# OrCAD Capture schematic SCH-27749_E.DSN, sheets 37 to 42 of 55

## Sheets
37 T4240 SerDes 1 & 2: size C
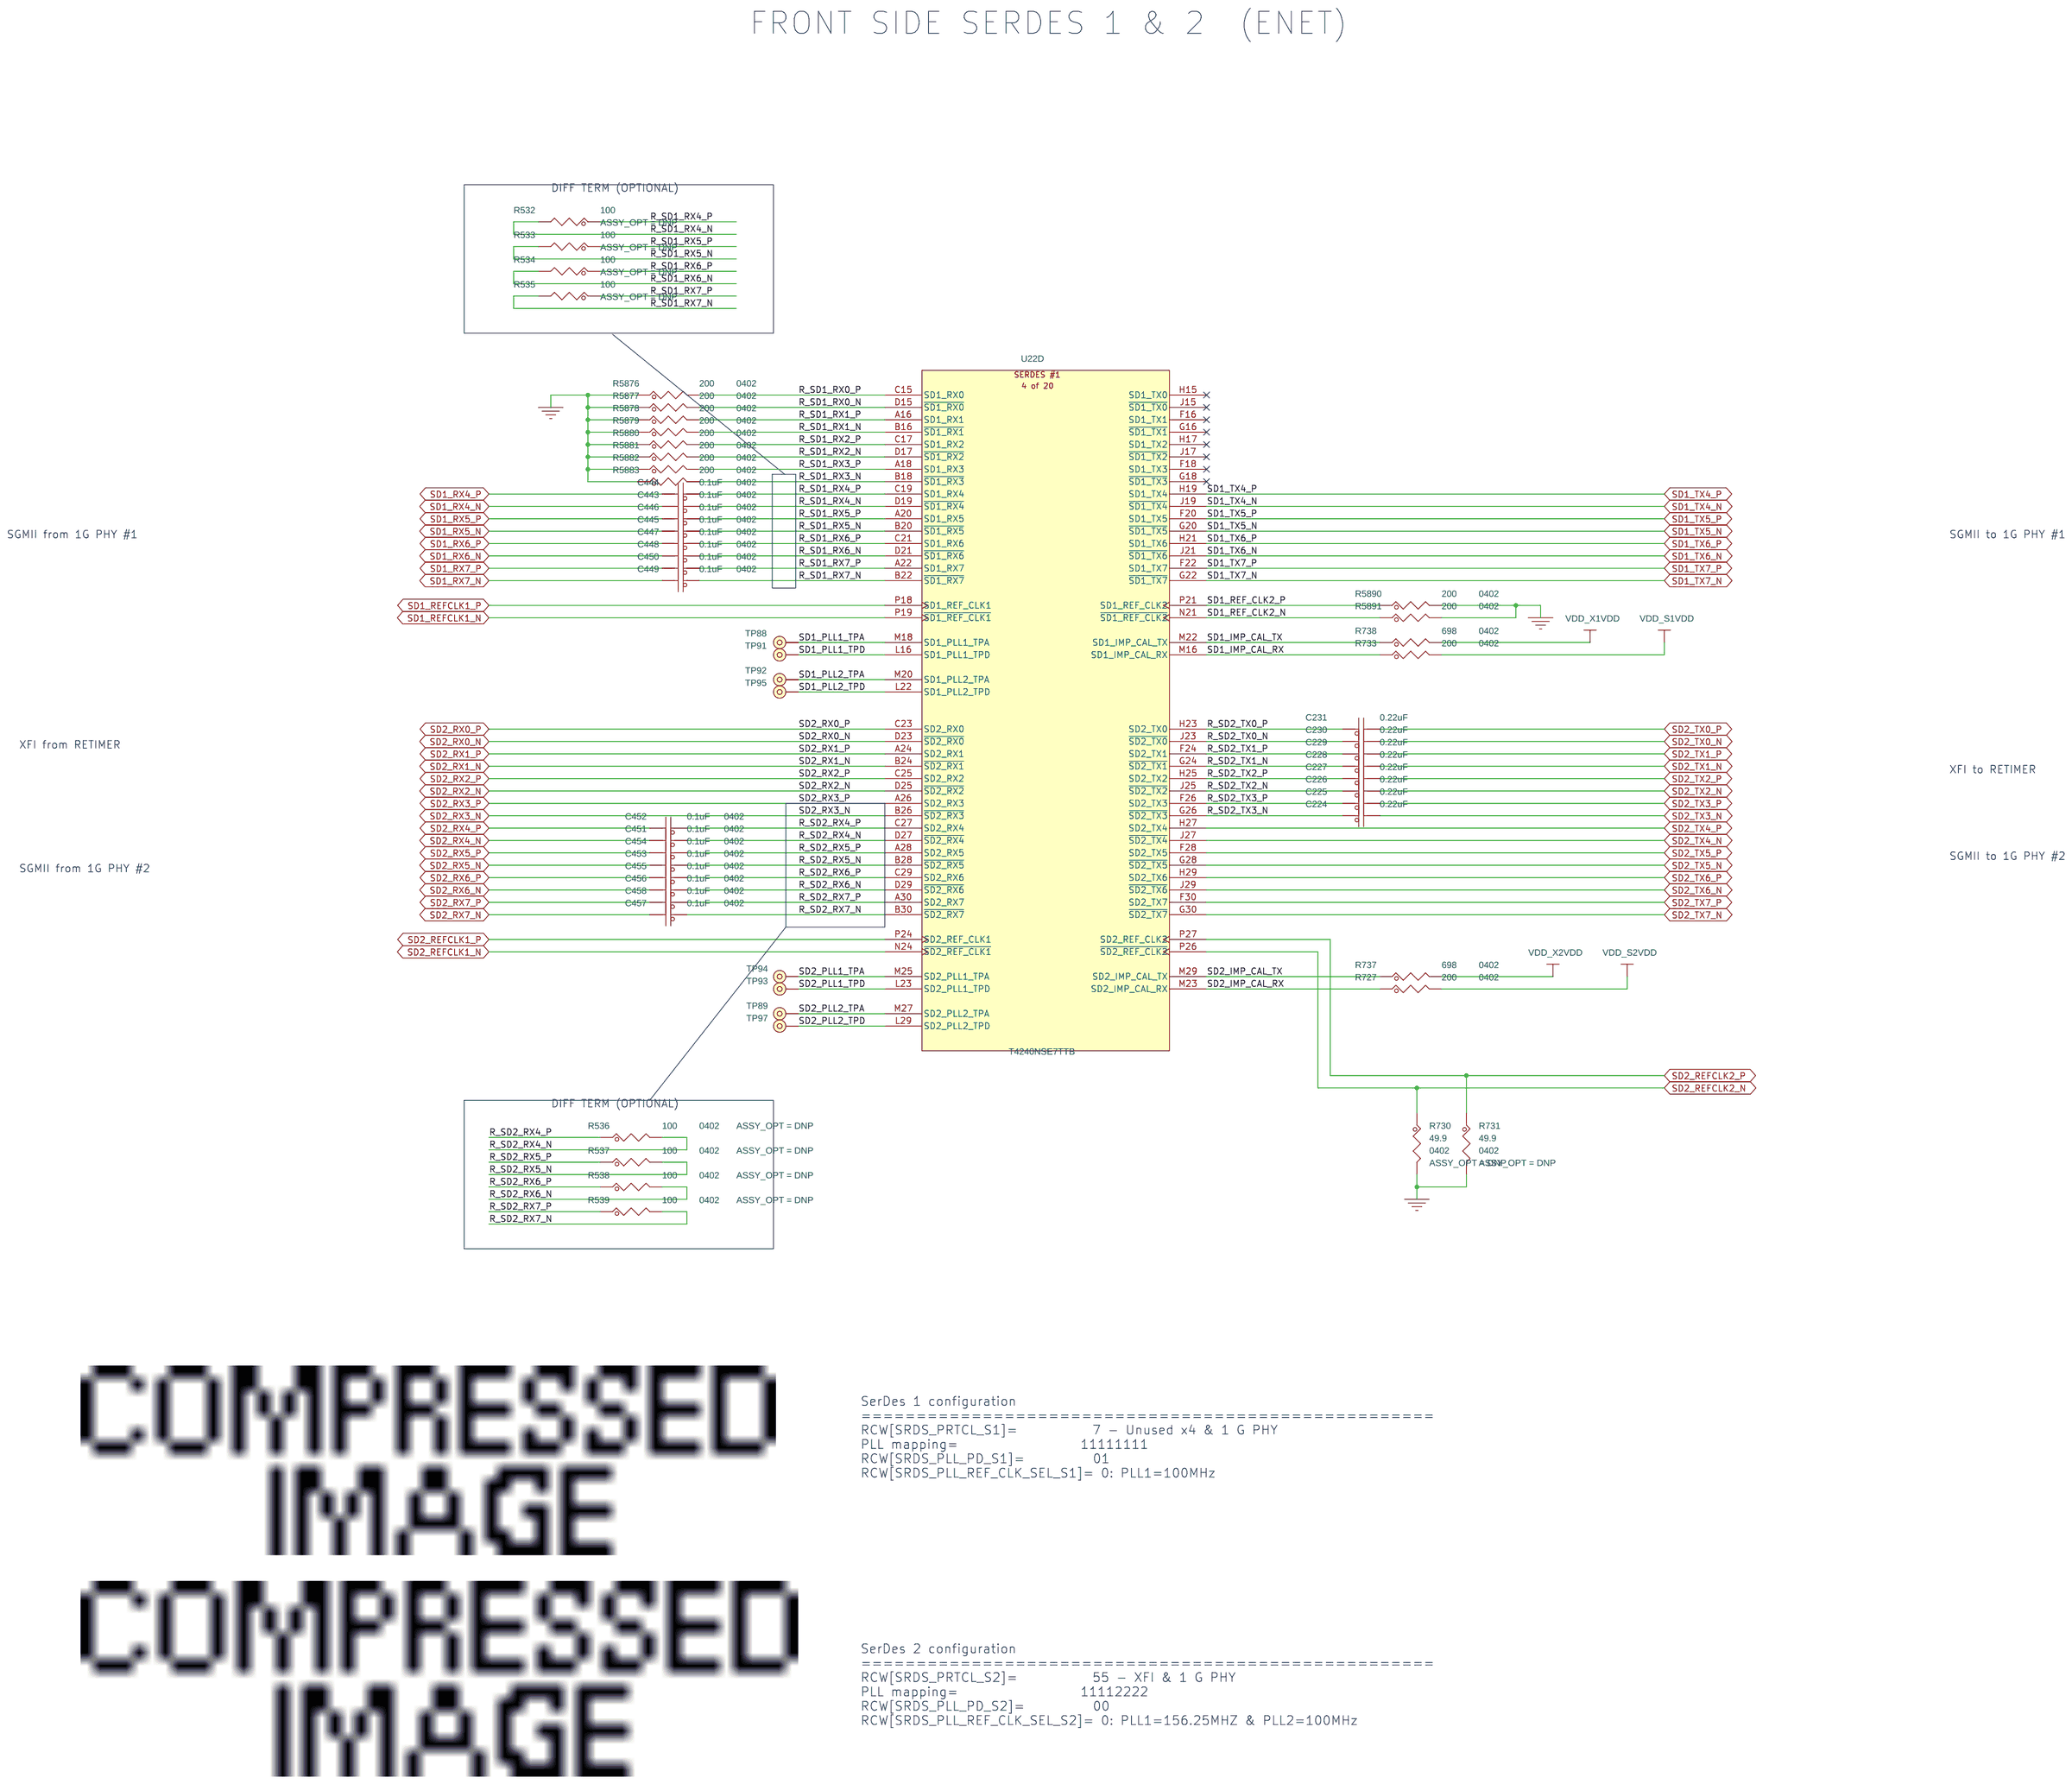
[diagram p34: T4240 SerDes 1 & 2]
38 10G Retimer: size C
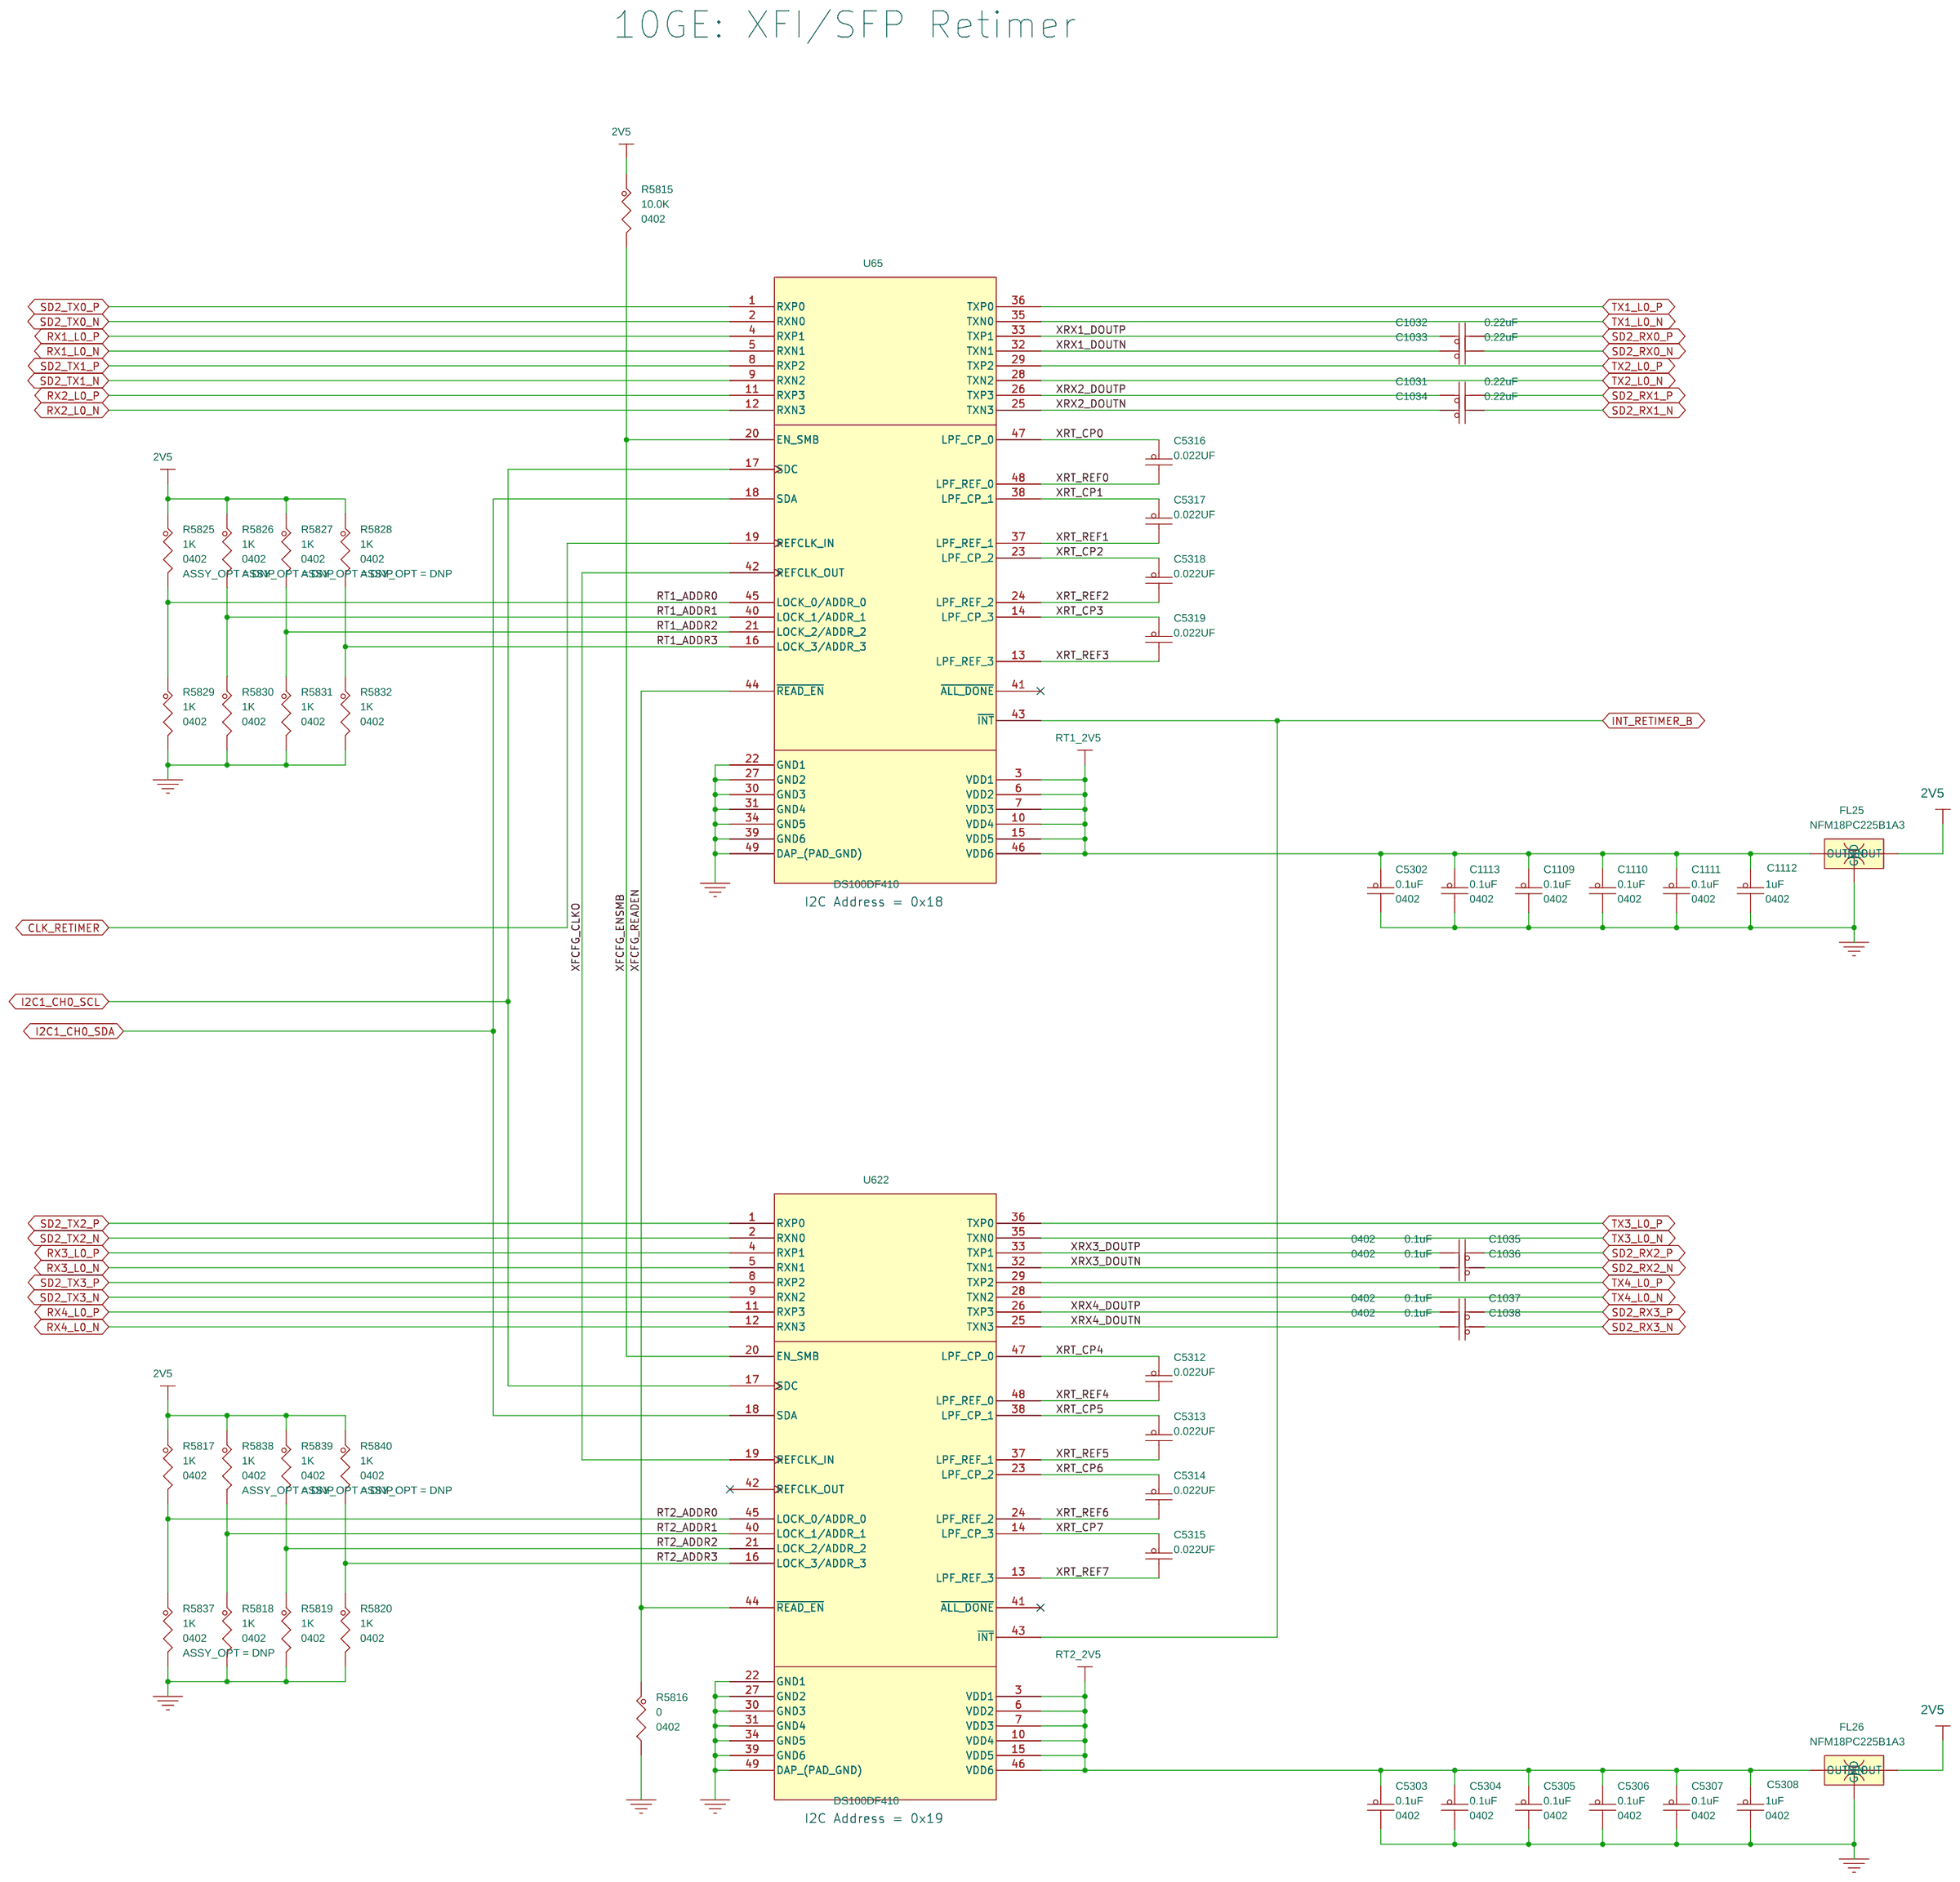
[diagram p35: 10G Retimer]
39 SFP Monitor/Control: size C
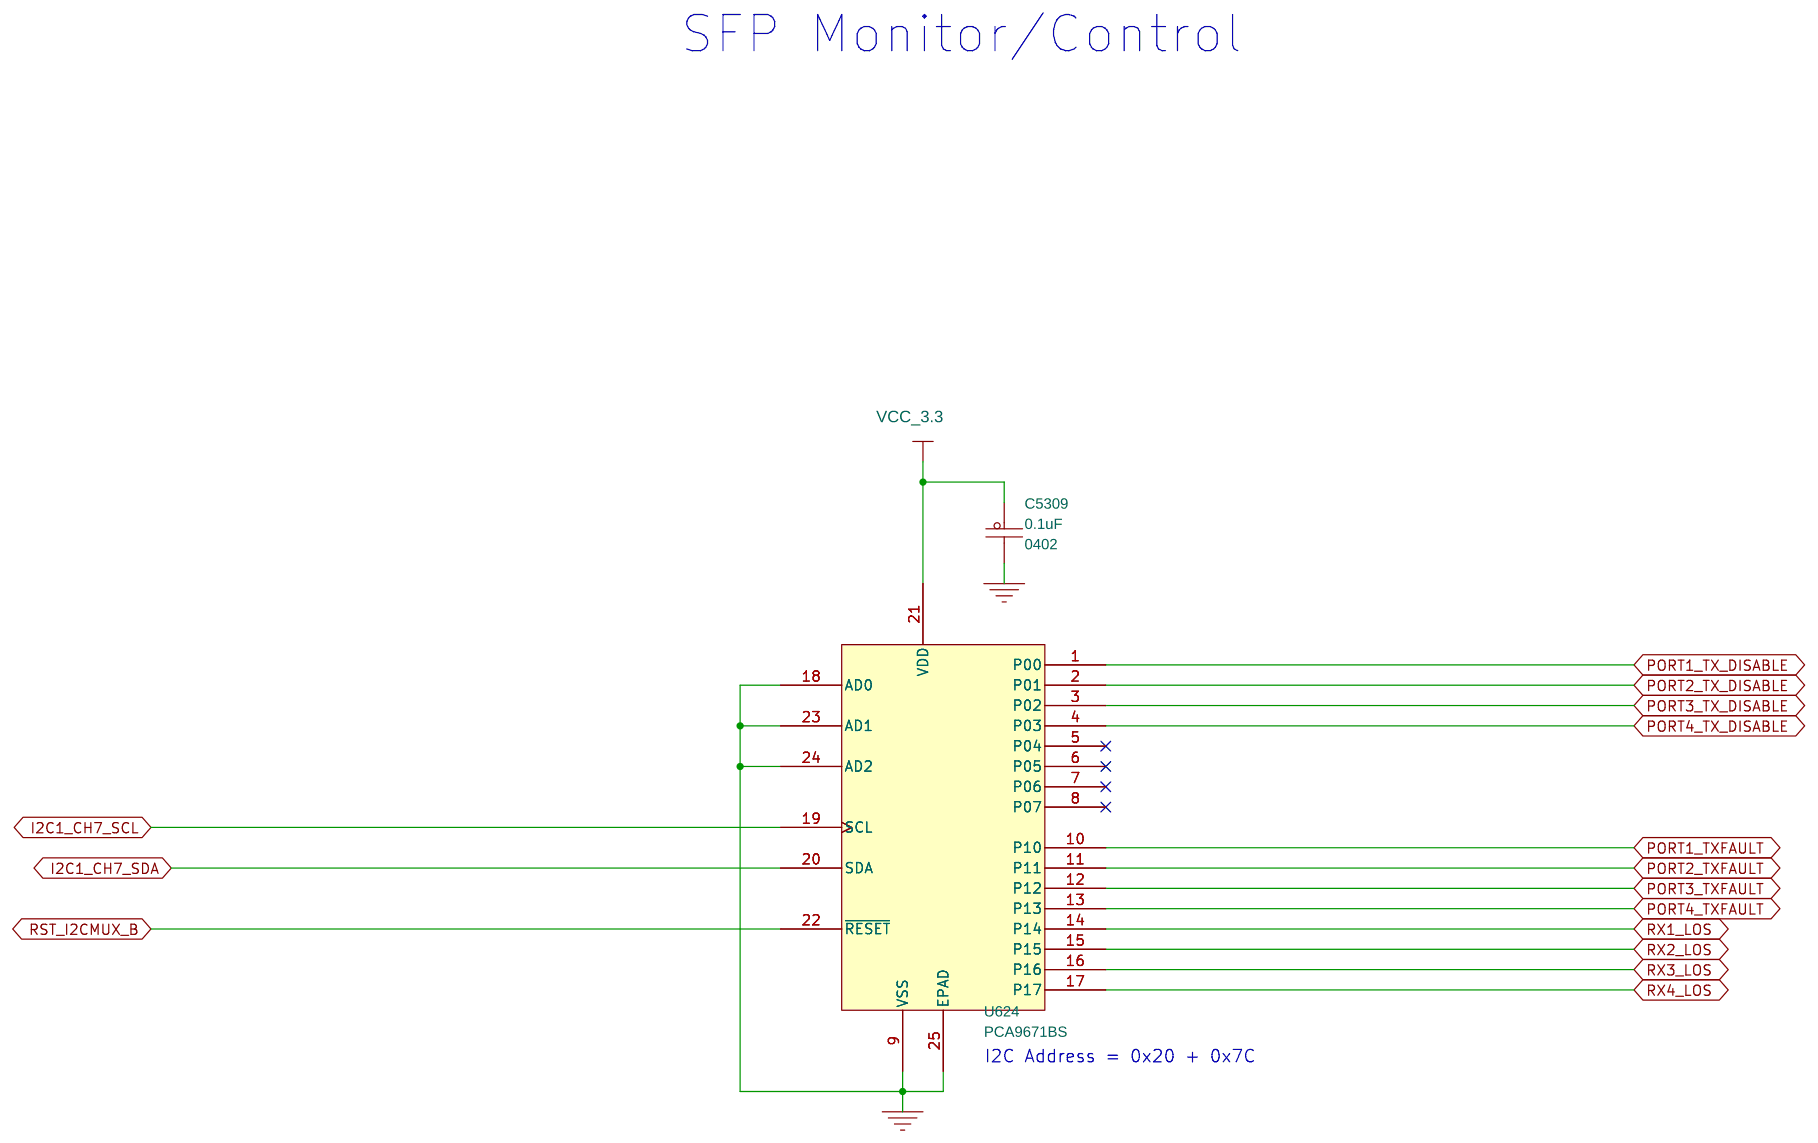
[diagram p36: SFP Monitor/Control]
40 SFP Ports 1&2 + Cage: size C
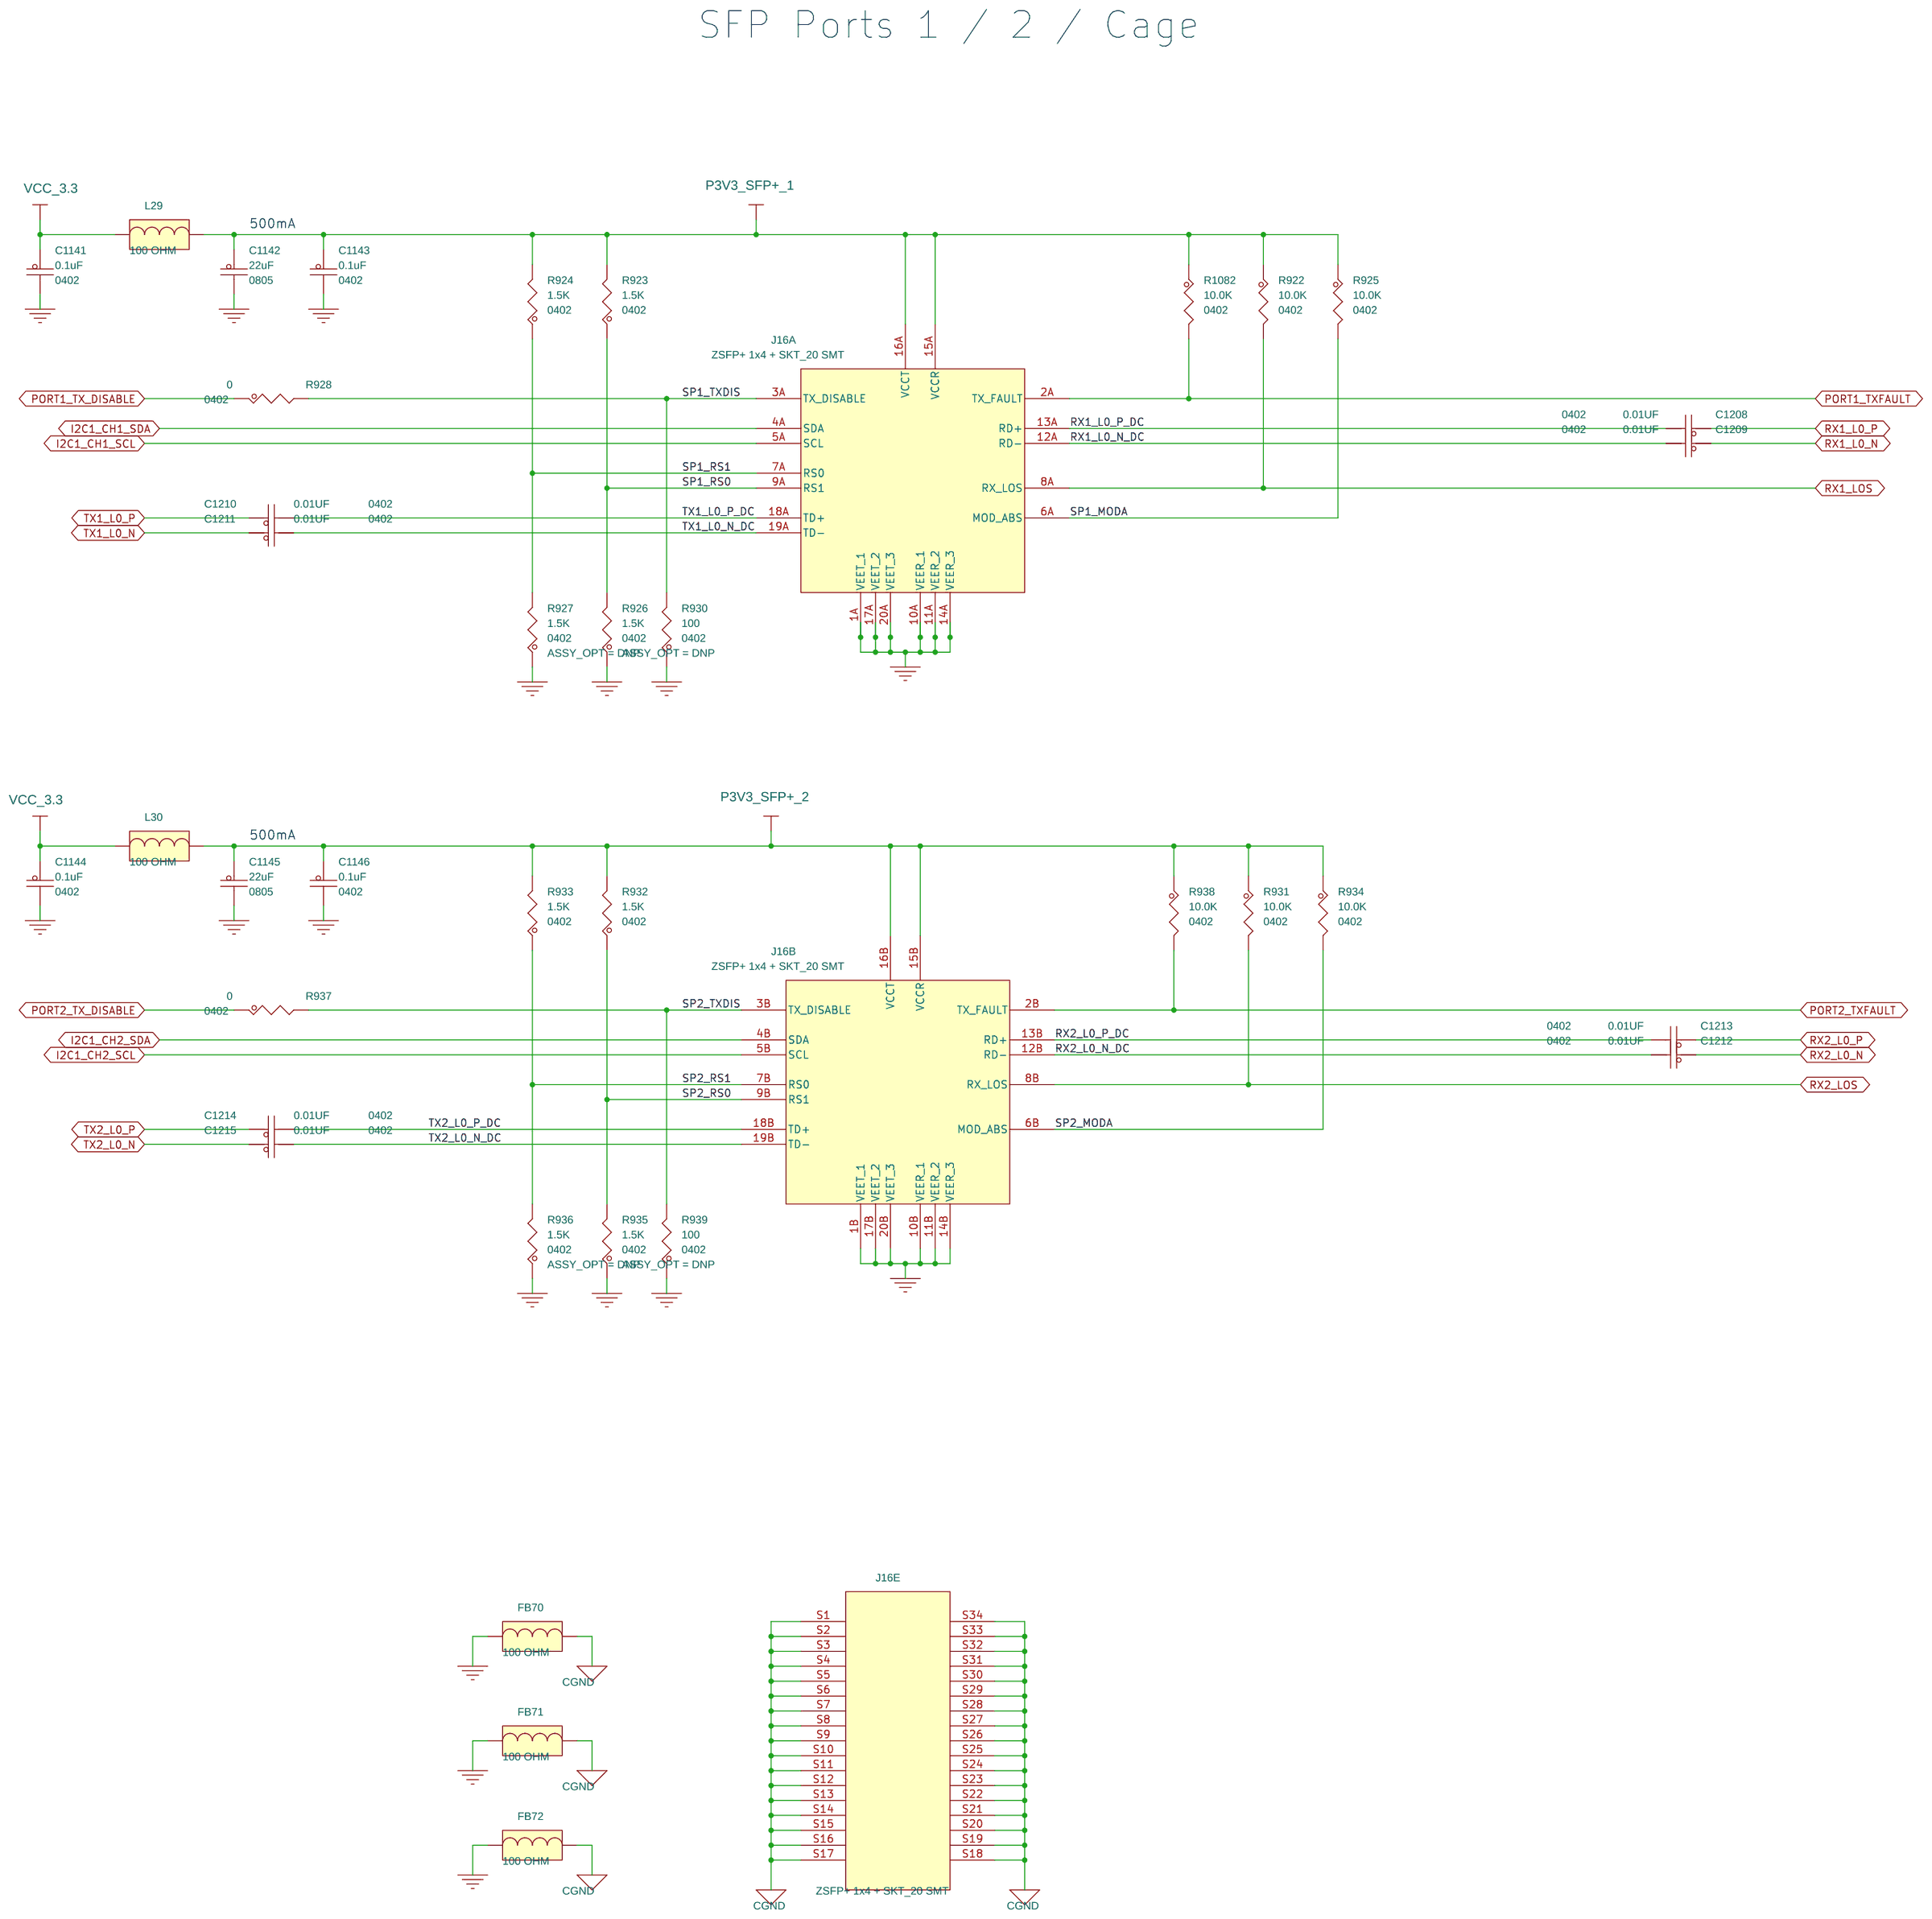
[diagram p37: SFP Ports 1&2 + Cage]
41 SFP Ports 3&4: size C
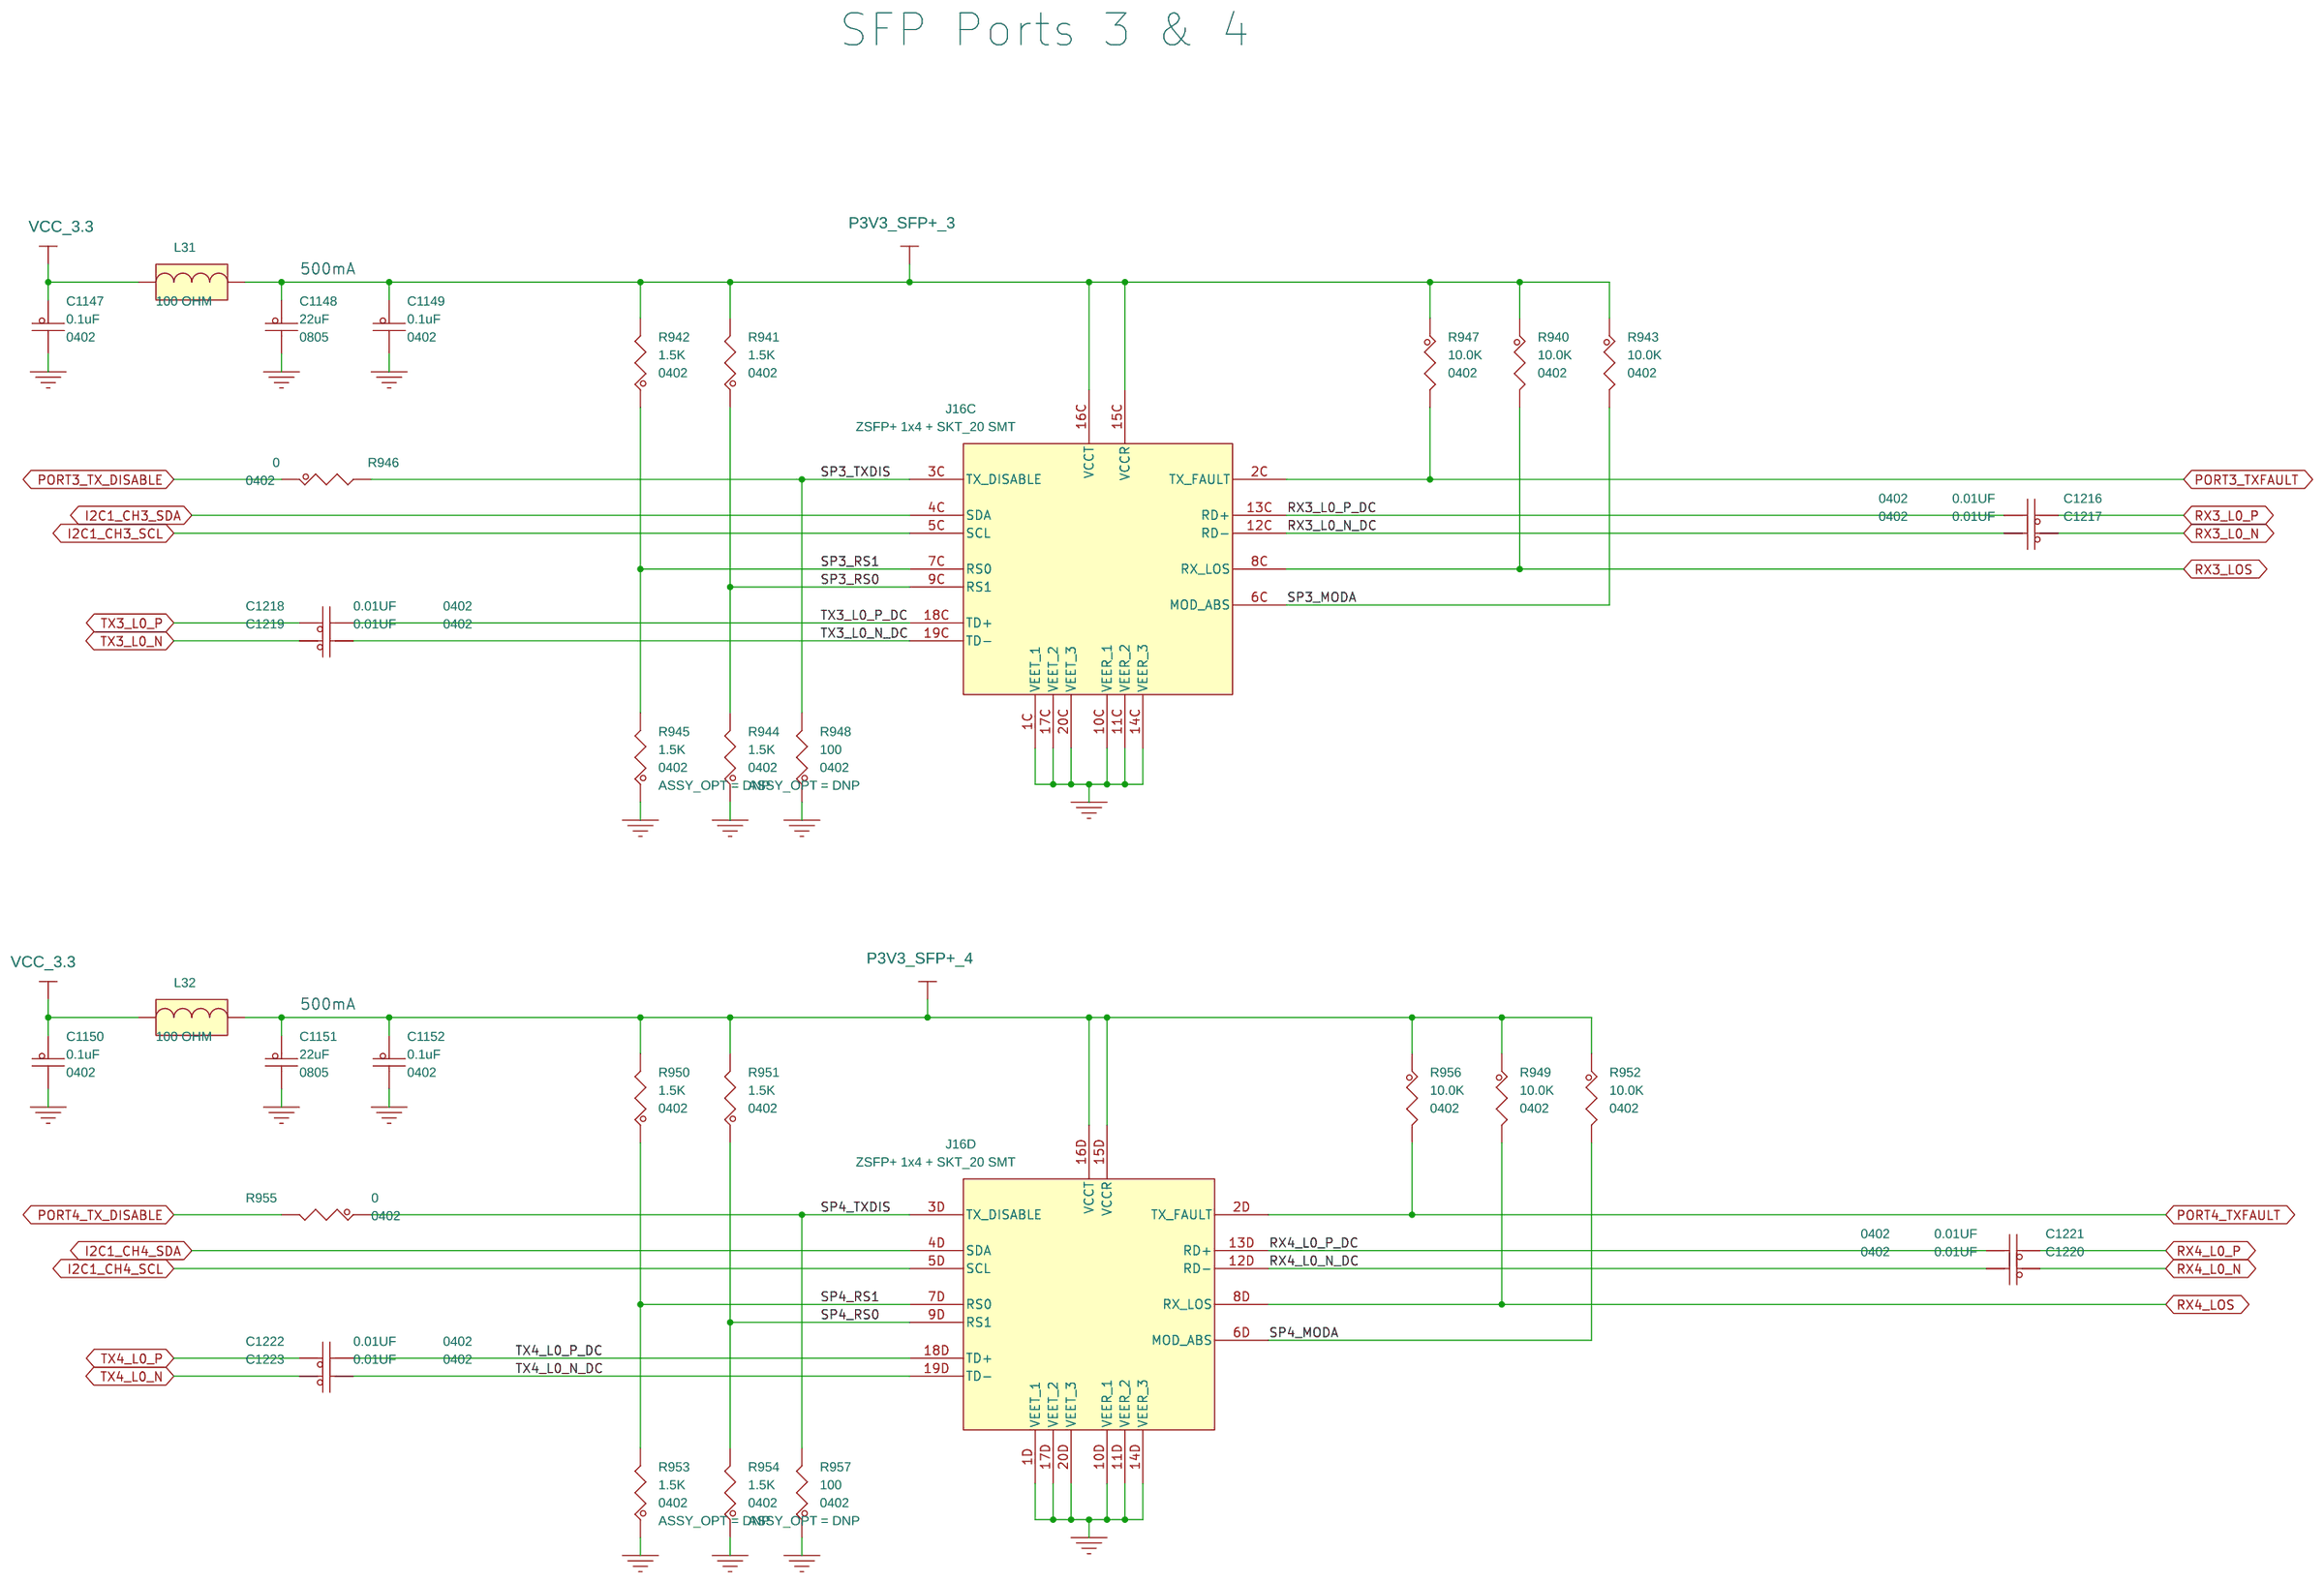
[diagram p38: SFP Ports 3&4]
42 88E1543 1G Phy #1: size C
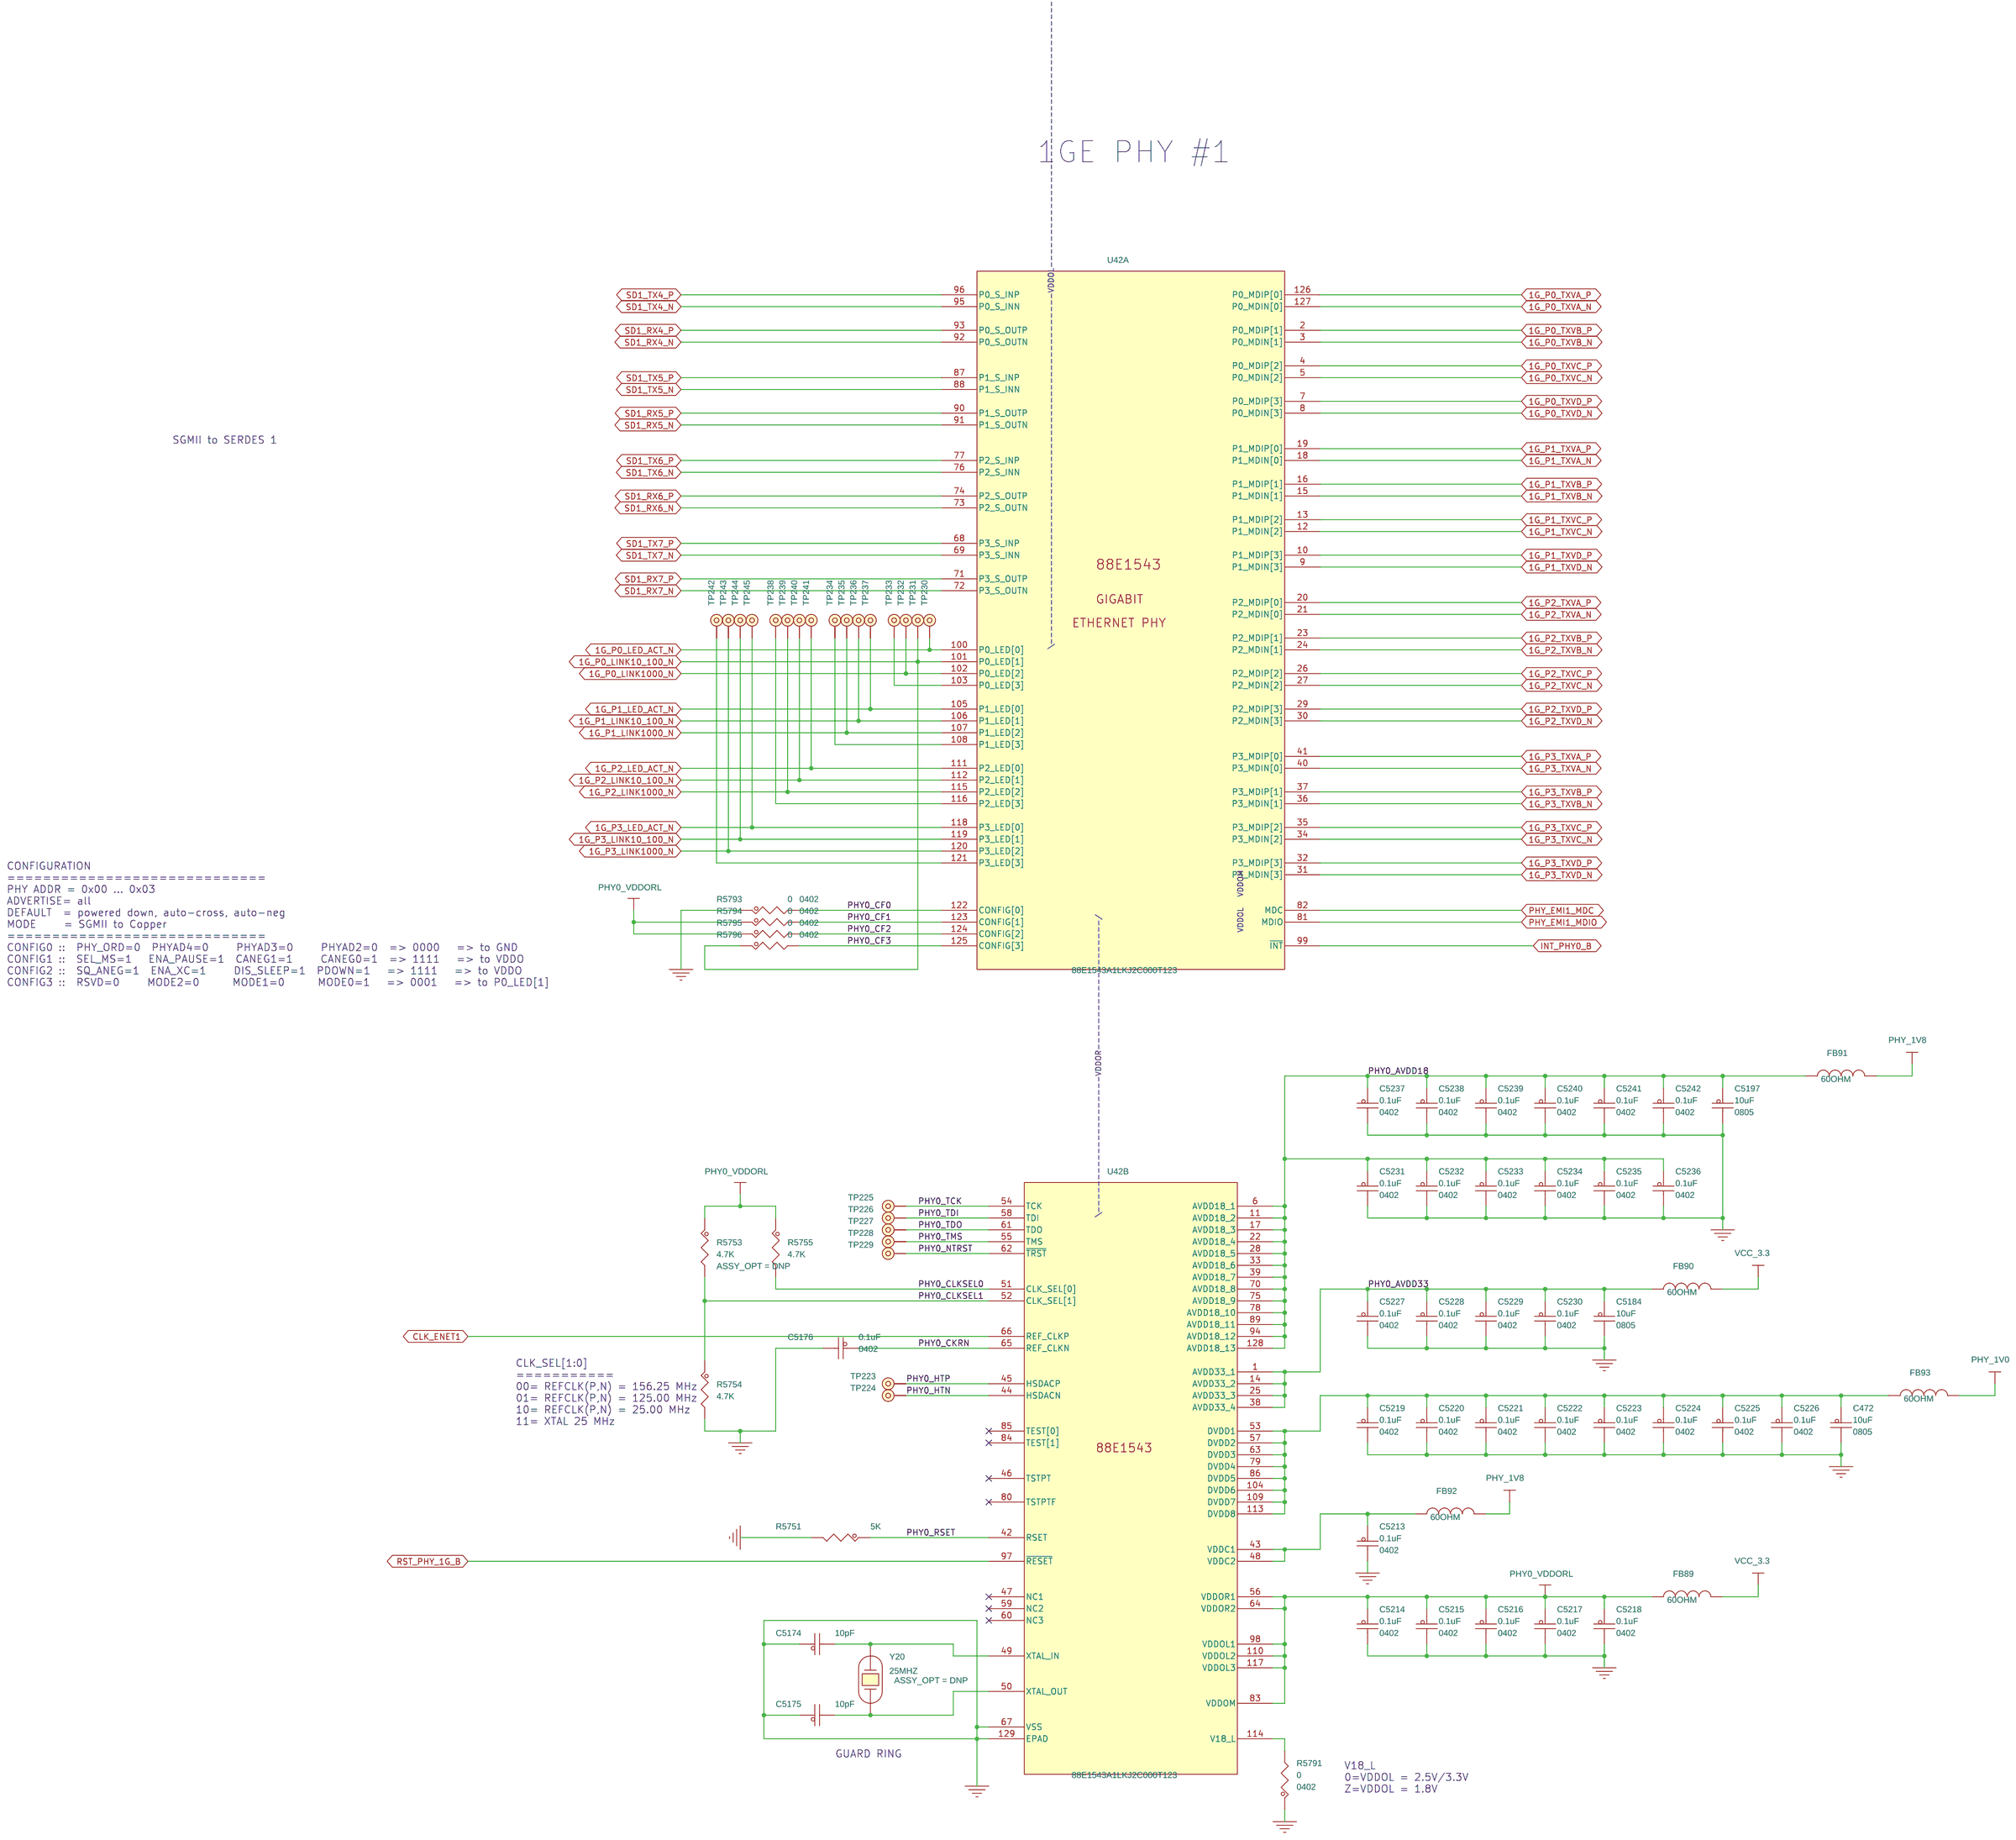
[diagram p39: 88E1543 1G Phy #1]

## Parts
sheet 10G Retimer
C1031  0.22uF  [CC0402_HD]
C1032  0.22uF  [CC0402_HD]
C1033  0.22uF  [CC0402_HD]
C1034  0.22uF  [CC0402_HD]
C1035  0.1uF  [CC0402_HD]
C1036  0.1uF  [CC0402_HD]
C1037  0.1uF  [CC0402_HD]
C1038  0.1uF  [CC0402_HD]
C1109  0.1uF  [CC0402_HD]
C1110  0.1uF  [CC0402_HD]
C1111  0.1uF  [CC0402_HD]
C1112  1uF  [CC0402_HD]
C1113  0.1uF  [CC0402_HD]
C5302  0.1uF  [CC0402_HD]
C5303  0.1uF  [CC0402_HD]
C5304  0.1uF  [CC0402_HD]
C5305  0.1uF  [CC0402_HD]
C5306  0.1uF  [CC0402_HD]
C5307  0.1uF  [CC0402_HD]
C5308  1uF  [CC0402_HD]
C5312  0.022UF  [CC0402_HD]
C5313  0.022UF  [CC0402_HD]
C5314  0.022UF  [CC0402_HD]
C5315  0.022UF  [CC0402_HD]
C5316  0.022UF  [CC0402_HD]
C5317  0.022UF  [CC0402_HD]
C5318  0.022UF  [CC0402_HD]
C5319  0.022UF  [CC0402_HD]
FL25  NFM18PC225B1A3  [cc0603_nfm18pc]
FL26  NFM18PC225B1A3  [cc0603_nfm18pc]
R5815  10.0K  [RC0402_25]
R5816  0  [RC0402_25]
R5817  1K  [RC0402_25]
R5818  1K  [RC0402_25]
R5819  1K  [RC0402_25]
R5820  1K  [RC0402_25]
R5825  1K  [RC0402_25]
R5826  1K  [RC0402_25]
R5827  1K  [RC0402_25]
R5828  1K  [RC0402_25]
R5829  1K  [RC0402_25]
R5830  1K  [RC0402_25]
R5831  1K  [RC0402_25]
R5832  1K  [RC0402_25]
R5837  1K  [RC0402_25]
R5838  1K  [RC0402_25]
R5839  1K  [RC0402_25]
R5840  1K  [RC0402_25]
U65  DS100DF410  [qfn48_0p5_7x7_ep5p1]
U622  DS100DF410  [qfn48_0p5_7x7_ep5p1]
sheet 88E1543 1G Phy #1
C472  10uF  [CC0603_OV]
C5174  10pF  [cc0402_hd]
C5175  10pF  [cc0402_hd]
C5176  0.1uF  [CC0402_HD]
C5184  10uF  [CC0603_OV]
C5197  10uF  [CC0603_OV]
C5213  0.1uF  [CC0402_HD]
C5214  0.1uF  [CC0402_HD]
C5215  0.1uF  [CC0402_HD]
C5216  0.1uF  [CC0402_HD]
C5217  0.1uF  [CC0402_HD]
C5218  0.1uF  [CC0402_HD]
C5219  0.1uF  [CC0402_HD]
C5220  0.1uF  [CC0402_HD]
C5221  0.1uF  [CC0402_HD]
C5222  0.1uF  [CC0402_HD]
C5223  0.1uF  [CC0402_HD]
C5224  0.1uF  [CC0402_HD]
C5225  0.1uF  [CC0402_HD]
C5226  0.1uF  [CC0402_HD]
C5227  0.1uF  [CC0402_HD]
C5228  0.1uF  [CC0402_HD]
C5229  0.1uF  [CC0402_HD]
C5230  0.1uF  [CC0402_HD]
C5231  0.1uF  [CC0402_HD]
C5232  0.1uF  [CC0402_HD]
C5233  0.1uF  [CC0402_HD]
C5234  0.1uF  [CC0402_HD]
C5235  0.1uF  [CC0402_HD]
C5236  0.1uF  [CC0402_HD]
C5237  0.1uF  [CC0402_HD]
C5238  0.1uF  [CC0402_HD]
C5239  0.1uF  [CC0402_HD]
C5240  0.1uF  [CC0402_HD]
C5241  0.1uF  [CC0402_HD]
C5242  0.1uF  [CC0402_HD]
FB89  60OHM  [ind_1p8x1mm_sm]
FB90  60OHM  [ind_1p8x1mm_sm]
FB91  60OHM  [ind_1p8x1mm_sm]
FB92  60OHM  [ind_1p8x1mm_sm]
FB93  60OHM  [ind_1p8x1mm_sm]
R5751  5K  [RC0402_25]
R5753  4.7K  [RC0402_25]
R5754  4.7K  [RC0402_25]
R5755  4.7K  [RC0402_25]
R5791  0  [RC0402_25]
R5793  0  [RC0402_25]
R5794  0  [RC0402_25]
R5795  0  [RC0402_25]
R5796  0  [RC0402_25]
TP223  TPAD_020  [tpad_020_top]
TP224  TPAD_020  [tpad_020_top]
TP225  TPAD_020  [tpad_020_top]
TP226  TPAD_020  [tpad_020_top]
TP227  TPAD_020  [tpad_020_top]
TP228  TPAD_020  [tpad_020_top]
TP229  TPAD_020  [tpad_020_top]
TP230  TPAD_020  [tpad_020_top]
TP231  TPAD_020  [tpad_020_top]
TP232  TPAD_020  [tpad_020_top]
TP233  TPAD_020  [tpad_020_top]
TP234  TPAD_020  [tpad_020_top]
TP235  TPAD_020  [tpad_020_top]
TP236  TPAD_020  [tpad_020_top]
TP237  TPAD_020  [tpad_020_top]
TP238  TPAD_020  [tpad_020_top]
TP239  TPAD_020  [tpad_020_top]
TP240  TPAD_020  [tpad_020_top]
TP241  TPAD_020  [tpad_020_top]
TP242  TPAD_020  [tpad_020_top]
TP243  TPAD_020  [tpad_020_top]
TP244  TPAD_020  [tpad_020_top]
TP245  TPAD_020  [tpad_020_top]
U42  88E1543A1LKJ2C000T123  [lqfp128_0p5_20x14_epad]  (sections A,B)
Y20  25MHZ  [xtal2_3p3x2p6]
sheet SFP Monitor/Control
C5309  0.1uF  [CC0402_HD]
U624  PCA9671BS  [qfn24_4X4_ep2p25mm]
sheet SFP Ports 1&2 + Cage
C1141  0.1uF  [CC0402_HD]
C1142  22uF  [CC0603_OV]
C1143  0.1uF  [CC0402_HD]
C1144  0.1uF  [CC0402_HD]
C1145  22uF  [CC0603_OV]
C1146  0.1uF  [CC0402_HD]
C1208  0.01UF  [CC0402_HD]
C1209  0.01UF  [CC0402_HD]
C1210  0.01UF  [CC0402_HD]
C1211  0.01UF  [CC0402_HD]
C1212  0.01UF  [CC0402_HD]
C1213  0.01UF  [CC0402_HD]
C1214  0.01UF  [CC0402_HD]
C1215  0.01UF  [CC0402_HD]
FB70  100 OHM  [IND_0805]
FB71  100 OHM  [IND_0805]
FB72  100 OHM  [IND_0805]
L29  100 OHM  [IND_0805]
L30  100 OHM  [IND_0805]
R922  10.0K  [RC0402_25]
R923  1.5K  [RC0402_25]
R924  1.5K  [RC0402_25]
R925  10.0K  [RC0402_25]
R926  1.5K  [RC0402_25]
R927  1.5K  [RC0402_25]
R928  0  [RC0402_25]
R930  100  [RC0402_25]
R931  10.0K  [RC0402_25]
R932  1.5K  [RC0402_25]
R933  1.5K  [RC0402_25]
R934  10.0K  [RC0402_25]
R935  1.5K  [RC0402_25]
R936  1.5K  [RC0402_25]
R937  0  [RC0402_25]
R938  10.0K  [RC0402_25]
R939  100  [RC0402_25]
R1082  10.0K  [RC0402_25]
sheet SFP Ports 3&4
C1147  0.1uF  [CC0402_HD]
C1148  22uF  [CC0603_OV]
C1149  0.1uF  [CC0402_HD]
C1150  0.1uF  [CC0402_HD]
C1151  22uF  [CC0603_OV]
C1152  0.1uF  [CC0402_HD]
C1216  0.01UF  [CC0402_HD]
C1217  0.01UF  [CC0402_HD]
C1218  0.01UF  [CC0402_HD]
C1219  0.01UF  [CC0402_HD]
C1220  0.01UF  [CC0402_HD]
C1221  0.01UF  [CC0402_HD]
C1222  0.01UF  [CC0402_HD]
C1223  0.01UF  [CC0402_HD]
J16  ZSFP+ 1x4 + SKT_20 SMT  [subassy_sfp_34_cage_1x4_49p8x61p85]  (sections A,B,C,D,E)
L31  100 OHM  [IND_0805]
L32  100 OHM  [IND_0805]
R940  10.0K  [RC0402_25]
R941  1.5K  [RC0402_25]
R942  1.5K  [RC0402_25]
R943  10.0K  [RC0402_25]
R944  1.5K  [RC0402_25]
R945  1.5K  [RC0402_25]
R946  0  [RC0402_25]
R947  10.0K  [RC0402_25]
R948  100  [RC0402_25]
R949  10.0K  [RC0402_25]
R950  1.5K  [RC0402_25]
R951  1.5K  [RC0402_25]
R952  10.0K  [RC0402_25]
R953  1.5K  [RC0402_25]
R954  1.5K  [RC0402_25]
R955  0  [RC0402_25]
R956  10.0K  [RC0402_25]
R957  100  [RC0402_25]
sheet T4240 DDR Controller #2
U22  T4240NSE7TTB  [BGA1932_1MM_45X45MM]  (sections A,B,C,D,E,F,G,H,I,J,K,L,M,N,O,P,Q,R,S,T)
sheet T4240 SerDes 1 & 2
C224  0.22uF  [CC0402_HD]
C225  0.22uF  [CC0402_HD]
C226  0.22uF  [CC0402_HD]
C227  0.22uF  [CC0402_HD]
C228  0.22uF  [CC0402_HD]
C229  0.22uF  [CC0402_HD]
C230  0.22uF  [CC0402_HD]
C231  0.22uF  [CC0402_HD]
C443  0.1uF  [CC0402_HD]
C444  0.1uF  [CC0402_HD]
C445  0.1uF  [CC0402_HD]
C446  0.1uF  [CC0402_HD]
C447  0.1uF  [CC0402_HD]
C448  0.1uF  [CC0402_HD]
C449  0.1uF  [CC0402_HD]
C450  0.1uF  [CC0402_HD]
C451  0.1uF  [CC0402_HD]
C452  0.1uF  [CC0402_HD]
C453  0.1uF  [CC0402_HD]
C454  0.1uF  [CC0402_HD]
C455  0.1uF  [CC0402_HD]
C456  0.1uF  [CC0402_HD]
C457  0.1uF  [CC0402_HD]
C458  0.1uF  [CC0402_HD]
R532  100  [RC0402_25]
R533  100  [RC0402_25]
R534  100  [RC0402_25]
R535  100  [RC0402_25]
R536  100  [RC0402_25]
R537  100  [RC0402_25]
R538  100  [RC0402_25]
R539  100  [RC0402_25]
R727  200  [RC0402_25]
R730  49.9  [RC0402_25]
R731  49.9  [RC0402_25]
R733  200  [RC0402_25]
R737  698  [RC0402_25]
R738  698  [RC0402_25]
R5876  200  [RC0402_25]
R5877  200  [RC0402_25]
R5878  200  [RC0402_25]
R5879  200  [RC0402_25]
R5880  200  [RC0402_25]
R5881  200  [RC0402_25]
R5882  200  [RC0402_25]
R5883  200  [RC0402_25]
R5890  200  [RC0402_25]
R5891  200  [RC0402_25]
TP88  TPAD_020  [tpad_020_top]
TP89  TPAD_020  [tpad_020_top]
TP91  TPAD_020  [tpad_020_top]
TP92  TPAD_020  [tpad_020_top]
TP93  TPAD_020  [tpad_020_top]
TP94  TPAD_020  [tpad_020_top]
TP95  TPAD_020  [tpad_020_top]
TP97  TPAD_020  [tpad_020_top]

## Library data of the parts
C224-C231 C1031-C1034 = CAP_NP: CAP CER 0.22uF 10V 10% X7R AEC-Q200 0402; 3D_Mechanical_Footprint_File: http://fcl.am.freescale.net/ALLEGRO/step/cc0402_25.STEP; AGILE_PN: 150-79031; CAD_APPROVED: Yes; FPLIST: CC0402_25,CC0402_HD,0402_CC,capc0402_l; HEIGHT: 0.55MM; MFG_NAME01: MURATA; MFG_PN01: GRT155R71A224KE01D; ROHS: Yes; Rated Voltage: 10V; Temp Range: -55C to +125C; Tolerance: 10%
C443-C458 C1035-C1038 C1109-C1111 C1113 C1141 C1143 C1144 C1146 C1147 C1149 C1150 C1152 C5176 C5213-C5242 C5302-C5307 C5309 = CAP_NP: CAP CER 0.1uF 16V 10% X7R AEC-Q200 0402; AGILE_PN: 150-79025; CAD_APPROVED: Yes; FPLIST: CC0402_25,CC0402_HD,0402_CC,capc0402_l; HEIGHT: 0.55MM; MFG_NAME01: MURATA; MFG_PN01: GCM155R71C104KA55D; Package: 0402; Package Size: 0402; Package Type: ø180mm Reel PAPER; Part Number: 4CC104B163X00; Product Name: (H)MLCC 0.1uF/16V +-10% 0402 X7R; ROHS: Yes; Rated Voltage: 16V; Temp Range: -55C to +125C; Tolerance: 10%
C1112 C5308 = CAP_NP: CAP CER 1uF 10V 10% X7S 0402; AGILE_PN: 150-80357; CAD_APPROVED: Yes; FPLIST: CC0402_25,CC0402_HD,0402_CC,capc0402_l; HEIGHT: 0.6MM; MFG_NAME01: MURATA; MFG_PN01: GRM155C71A105KE11D; Package: 0402; Package Size: 0402; Part Number: 4CC105B101X00; Product Name: (H)MLCC 1uF/10V +-10% 0402 X5R; ROHS: Yes; Rated Voltage: 10V; Temp Range: -55C to +125C; Tolerance: 10%
C5312-C5319 = CAP_NP: CAP CER 0.022UF 16V 10% X7R 0402; AGILE_PN: 150-30293; CAD_APPROVED: Yes; FPLIST: CC0402_25,CC0402_HD,0402_CC,capc0402_l; HEIGHT: 0.56MM; MFG_NAME01: AVX; MFG_PN01: 0402YC223KAT2A; ROHS: Yes; Rated Voltage: 16V; Temp Range: -55C to +125C; Tolerance: 10%; VOLTAGE: 16V
FL25 FL26 = NFM18PC225B1A3: CAP FILTER EMI 2.2uF 10V 20% -- 0603; 3D_Mechanical_Footprint_File: http://fcl.am.freescale.net/ALLEGRO/step/cc0603_nfm18pc.STEP; AGILE_PN: 150-79428; CAD_APPROVED: Yes; HEIGHT: 0.9MM; MFG_NAME01: MURATA; MFG_PN01: NFM18PC225B1A3D; ROHS: Yes; Rated Voltage: 10V; Temp Range: -40C to +85C; Temp_Range: -40 C to +85 C; Tolerance: 20%; VOLTAGE: 10V
R922 R925 R931 R934 R938 R940 R943 R947 R949 R952 R956 R1082 R5815 = RES: RES MF 10.0K 1/16W 1% AEC-Q200 0402; AGILE_PN: 470-75416; CAD_APPROVED: Yes; FPLIST: RC0402_25,RC0402_HD,0402_CC; HEIGHT: 0.4MM; MFG_NAME01: KOA SPEER; MFG_PN01: RK73H1ETTP1002F; Package: 0402; Part Number: 4RC1003B11X00; Product Name: (H)RES 10K 1/16W 0402 1% PBFREE; ROHS: Yes; Temp Range: –55 °C to +155 °C; Tolerance: 1%
R928 R937 R946 R955 R5791 R5793-R5796 R5816 = RES: RES MF ZERO OHM 1/10W -- 0402; AGILE_PN: 470-79965; CAD_APPROVED: Yes; FPLIST: RC0402_25,RC0402_HD,RC0402_X2,0402_CC,RC0402_X3; HEIGHT: 0.4MM; MFG_NAME01: PANASONIC; MFG_PN01: ERJ-2GE0R00X; Package: 0402; Part Number: 4RC0000B51X00; Product Name: (H)RES 0E 1/16W 0402 5% PBFREE; ROHS: Yes; Temp Range: –55 °C to +155 °C
R5817-R5820 R5829-R5832 = RES: RES 1K 1/16W 5% 0402; AGILE_PN: 470-80721; CAD_APPROVED: Yes; FPLIST: RC0402_25,RC0402_HD,0402_CC; HEIGHT: 0.4 MM; MFG_NAME01: TE CONNECTIVITY LTD; MFG_PN01: CRG0402J1K0; Package: 0402; Part Number: 4RC1002B11X00; Product Name: (H)RES 1K 1/16W 0402 1% PBFREE; ROHS: Yes; Tolerance: 5%
R5825-R5828 R5837-R5840 = RES: RES 1K 1/16W 5% 0402; AGILE_PN: 470-80721; ASSY_OPT: DNP; CAD_APPROVED: Yes; FPLIST: RC0402_25,RC0402_HD,0402_CC; HEIGHT: 0.4 MM; MFG_NAME01: TE CONNECTIVITY LTD; MFG_PN01: CRG0402J1K0; Package: 0402; Part Number: 4RC1002B11X00; Product Name: (H)RES 1K 1/16W 0402 1% PBFREE; ROHS: Yes; Tolerance: 5%
U65 U622 = DS100RT410_48P: IC RETIMER QUAD CH W/ ADAPTIVE EQ CDR & DFE 10GbE 2.5V QFN48; 3D_Mechanical_Footprint_File: http://fcl.am.freescale.net/ALLEGRO/step/qfn48_0p5_7x7_ep5p1.STEP; AGILE_PN: 312-81711; CAD_APPROVED: Yes; HEIGHT: 0.8MM; MFG_NAME01: TEXAS INSTRUMENTS; MFG_PN01: DS100DF410SQ/NOPB; ROHS: Yes; Temp Range: -40C to +85C; VOLTAGE: 2.375-2.625V
C472 C5184 C5197 = CAP_NP: CAP CER 10UF 10V 10% X5R 0603; AGILE_PN: 150-78675; CAD_APPROVED: Yes; FPLIST: CC0603_OV,CC0603,0603_CC_NSP; HEIGHT: 1.016MM; MFG_NAME01: MURATA; MFG_PN01: GRM188R61A106KE69D; Package: 0805; Part Number: 4CC106D101X00; Product Name: (H)MLCC 10uF/10V +/-10% 0805 X5R; ROHS: Yes; Rated Voltage: 10V; Temp Range: -55C to +85C; Tolerance: 10%
C5174 C5175 = CAP_NP: CAP CER 10pF 50V 1% C0G AEC-Q200 0402; 3D_Mechanical_Footprint_File: http://fcl.am.freescale.net/ALLEGRO/step/cc0402_25.STEP; AGILE_PN: 150-81416; CAD_APPROVED: Yes; FPLIST: cc0402_25,cc0402_hd,0402_cc,capc0402_l; HEIGHT: 0.55MM; MFG_NAME01: MURATA; MFG_PN01: GCM1555C1H100FA16; Package Size: 0402; Package Type: SMD/SMT; ROHS: Yes; Rated Voltage: 50V; Temp Range: -55C to +125C; Tolerance: 1%
FB89-FB93 = INDUCTOR: IND FER BEAD 60OHM@100MHz 3A 25% 0603; 3D_Mechanical_Footprint_File: http://fcl.am.freescale.net/ALLEGRO/step/ind_1p8x1mm_sm.step; AGILE_PN: 180-78461; CAD_APPROVED: Yes; HEIGHT: 1MM; MFG_NAME01: WURTH ELEKTRONIK EISOS GMBH & CO. KG (ELECTRONIC & ELECTROMEHANICAL COMP); MFG_PN01: 742792602; ROHS: Yes
R5751 = RES: RES MF 5K 1/16W 1% 0402; AGILE_PN: 470-82785; CAD_APPROVED: Yes; FPLIST: RC0402_25,RC0402_HD,0402_CC; HEIGHT: 0.40MM; MFG_NAME01: YAGEO AMERICA; MFG_PN01: RC0402FR-075KL; Package Size: 0402 (1005 Metric); Tolerance: 1%
R5753 = RES: RES MF 4.7K 1/10W 5% AEC-Q200 0402; AGILE_PN: 470-82064; ASSY_OPT: DNP; CAD_APPROVED: Yes; FPLIST: RC0402_25,RC0402_HD,0402_CC,RC0402_X2; HEIGHT: 0.41mm; MFG_NAME01: KOA SPEER; MFG_PN01: RK73B1ETTP472J; ROHS: Yes; Temp Range: -55C to +155C; Tolerance: 5%
R5754 R5755 = RES: RES MF 4.7K 1/10W 5% AEC-Q200 0402; AGILE_PN: 470-82064; CAD_APPROVED: Yes; FPLIST: RC0402_25,RC0402_HD,0402_CC,RC0402_X2; HEIGHT: 0.41mm; MFG_NAME01: KOA SPEER; MFG_PN01: RK73B1ETTP472J; ROHS: Yes; Temp Range: -55C to +155C; Tolerance: 5%
TP88 TP89 TP91-TP95 TP97 TP223-TP245 = T_POINT_TH: TEST POINT PAD 20 MILS SMT, NOT PART TO ORDER; AGILE_PN: 211-81036; CAD_APPROVED: Yes; FPLIST: tpad_020_top,tpad_020_btm_nsp; HEIGHT: 0.127MM; MFG_NAME01: NO PART ORDER; MFG_PN01: NA; ROHS: Yes
U42 = IC_88E1543_LQFP_128P_EP: IC XCVR QUAD ETHERNET 10/100/1000 PHY 3.3V LQFP128; 3D_Mechanical_Footprint_File: http://fcl.am.freescale.net/ALLEGRO/step/lqfp128_0p5_20x14_epad.STEP; AGILE_PN: 312-81220; CAD_APPROVED: Yes; HEIGHT: 1.6MM; MFG_NAME01: MARVELL SEMICONDUCTOR INC; ROHS: Yes; VOLTAGE: 1.8/2.5/3.3V
Y20 = XTAL: XTAL 25MHZ 8PF -- AEC-Q200 SMT-2; 3D_Mechanical_Footprint_File: http://fcl.am.freescale.net/ALLEGRO/step/xtal2_3p3x2p6.STEP; AGILE_PN: 230-78297; ASSY_OPT: DNP; CAD_APPROVED: Yes; HEIGHT: 0.95MM; MFG_NAME01: KYOCERA; MFG_PN01: CX3225GA25000D0PTVCC; ROHS: Yes; Temp Range: -40°C to 150°C
U624 = PCA9671BS_HVQFN24: IC I/O EXPANDER 16BIT I2C 2.3-5.5V HVQFN24; 3D_Mechanical_Footprint_File: http://fcl.am.freescale.net/ALLEGRO/step/qfn24_4X4_ep2p25mm.STEP; AGILE_PN: 312-82287; CAD_APPROVED: Yes; HEIGHT: 1MM; MFG_NAME01: NXP SEMICONDUCTORS; MFG_PN01: PCA9671BS,118; ROHS: Yes; Temp Range: -40°C ~ 85°C; VOLTAGE: 2.3-5.5V
C1142 C1145 C1148 C1151 = CAP_NP: CAP CER 22uF 6.3V 20% X6S 0603; AGILE_PN: 150-79717; CAD_APPROVED: Yes; FPLIST: CC0603_OV,CC0603,0603_CC_NSP; HEIGHT: 1MM; MFG_NAME01: MURATA; MFG_PN01: GRM188C80J226ME15D; Package: 0805; Package Size: 0603; Package Type: 180mm ReelPAPER W8P4; Part Number: 4CC226D631X00; Product Name: (H)MLCC 22uF/6.3V +-20% 0805 X5R PBFREE; ROHS: Yes; Rated Voltage: 6.3V; Temp Range: -55C to +105C; Tolerance: 20%
C1208-C1223 = CAP_NP: CAP CER 0.01UF 50V 10% X7R 0402; AGILE_PN: 150-30114; CAD_APPROVED: Yes; FPLIST: CC0402_25,CC0402_HD,0402_CC,capc0402_l; HEIGHT: 0.55 MM; MFG_NAME01: MURATA; MFG_PN01: GRM155R71H103KA88D; Package: 0402; Part Number: 4CC103B501X00; Product Name: (H)MLCC 0.01uF/50V +-10% 0402 X7R; ROHS: Yes; Rated Voltage: 50V; Temp Range: -55C to +125C; Tolerance: 10%
FB70-FB72 L29-L32 = BEAD: IND FER BEAD 100OHM@100MHZ 4A 25% AEC-Q200 0805; AGILE_PN: 180-78923; CAD_APPROVED: Yes; HEIGHT: 1.05MM; MFG_NAME01: TDK; MFG_PN01: MPZ2012S101ATD25; Package Size: 2x1.25MM; ROHS: Yes; Temp Range: -55°C to +125°C
R923 R924 R932 R933 R941 R942 R950 R951 = RES: RES MF 1.50K 1/10W 1% AEC-Q200 0402; AGILE_PN: 470-81990; CAD_APPROVED: Yes; FPLIST: RC0402_25,RC0402_HD,0402_CC; HEIGHT: 0.4 MM; MFG_NAME01: KOA SPEER; MFG_PN01: RK73H1ETTP1501F; Package: 0402; Part Number: 4RC1502B11X00; Product Name: (H)RES 1.5K 1/16W 0402 1% PBFREE; ROHS: Yes; Temp Range: -55C to +155C; Tolerance: 1%
R926 R927 R935 R936 R944 R945 R953 R954 = RES: RES MF 1.50K 1/10W 1% AEC-Q200 0402; AGILE_PN: 470-81990; ASSY_OPT: DNP; CAD_APPROVED: Yes; FPLIST: RC0402_25,RC0402_HD,0402_CC; HEIGHT: 0.4 MM; MFG_NAME01: KOA SPEER; MFG_PN01: RK73H1ETTP1501F; Package: 0402; Part Number: 4RC1502B11X00; Product Name: (H)RES 1.5K 1/16W 0402 1% PBFREE; ROHS: Yes; Temp Range: -55C to +155C; Tolerance: 1%
R930 R939 R948 R957 = RES: RES MF 100 OHM 1/16W 1% AEC-Q200 0402; AGILE_PN: 470-80666; CAD_APPROVED: Yes; FPLIST: RC0402_25,RC0402_HD,0402_CC; HEIGHT: 0.4 MM; MFG_NAME01: KOA SPEER; MFG_PN01: RK73H1ETTP1000F; Package: 0402; Part Number: 4RC1001B11X00; Product Name: (H)RES 100E 1/16W 0402 1% PBFREE; ROHS: Yes
J16 = CON_SFPCAGE_1X4: SUBASSEMBLY CON 34 ZSFP+ CAGE 1X4 RA TH 0.8MM SP 493H -- 71L + CON 2X10 ZSFP RA 0.8MM SP 220H AU; AGILE_PN: 750-77892; CAD_APPROVED: Yes; HEIGHT: 12.52 MM; MFG_NAME01: SUBASSEMBLY; MFG_PN01: 210-81644,211-80124; ROHS: Yes
U22 = T4240: IC MPU 64BIT T4240 1.8GHz 1.025V CRYPTO QorIQ PBGA1932; 3D_Mechanical_Footprint_File: http://fcl.am.freescale.net/ALLEGRO/step/bga1932_1mm_45x45mm.STEP; AGILE_PN: 330-77243; CAD_APPROVED: Yes; HEIGHT: 3.33 MM; MFG_NAME01: NXP SEMICONDUCTOR; Package Size: SOT1645-1; Part Number: 71F101G206X01; Product Name: (N)SOC FREESCALE:T4240NSE7TTB; ROHS: Yes; Temp Range: 0 to 105 °C
R532-R539 = RES: RES MF 100 OHM 1/16W 1% AEC-Q200 0402; AGILE_PN: 470-80666; ASSY_OPT: DNP; CAD_APPROVED: Yes; FPLIST: RC0402_25,RC0402_HD,0402_CC; HEIGHT: 0.4 MM; MFG_NAME01: KOA SPEER; MFG_PN01: RK73H1ETTP1000F; Package: 0402; Part Number: 4RC1001B11X00; Product Name: (H)RES 100E 1/16W 0402 1% PBFREE; ROHS: Yes
R727 R733 R5876-R5883 R5890 R5891 = RES: RES MF 200 Ohm 1/16W 1% AEC-Q200 0402; AGILE_PN: 470-80516; CAD_APPROVED: Yes; FPLIST: RC0402_25,RC0402_HD,0402_CC; HEIGHT: 0.4 MM; MFG_NAME01: KOA SPEER; MFG_PN01: RK73H1ETTP2000F; Package: 0402; Part Number: 4RC2001B11X00; Product Name: (H)RES 200E 1/16W 0402 1% PBFREE; ROHS: Yes; Tolerance: 1%
R730 R731 = RES: RES MF 49.9 OHM 1/10W 1% AEC-Q200 0402; AGILE_PN: 470-82539; ASSY_OPT: DNP; CAD_APPROVED: YES; FPLIST: RC0402_25,RC0402_HD,0402_CC,RC0402_X2; HEIGHT: 0.4 MM; MFG_NAME01: PANASONIC; MFG_PN01: ERJ-2RKF49R9X; Package: 0402; Package Size: 0402 (1005 Metric); Part Number: 4RC4990B11X00; Product Name: (H)RES 49.9E 1/16W 0402 1% PBFREE; ROHS: YES; Temp Range: -55°C to 155°C; Tolerance: 1%
R737 R738 = RES: RES MF 698 OHM 1/16W 1% ACE-Q200 0402; AGILE_PN: 470-78342; CAD_APPROVED: Yes; FPLIST: RC0402_25,RC0402_HD,0402_CC; HEIGHT: 0.4MM; MFG_NAME01: KOA SPEER; MFG_PN01: RK73H1ETTP6980F; Package: 0402; Part Number: 4RC6981B11X00; Product Name: (H)RES 698E 1/16W 0402 1% PBFREE; ROHS: Yes; Tolerance: 1%

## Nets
2V5: FL25.1(IN_OUT) FL26.1(IN_OUT) R5815.1 R5817.1 R5825.1 R5826.1 R5827.1 R5828.1 R5838.1 R5839.1 R5840.1 ; also on sheet 15 20 24 45
GND: C472.2 C1109.2 C1110.2 C1111.2 C1112.2 C1113.2 C1141.2 C1142.2 C1143.2 C1144.2 C1145.2 C1146.2 C1147.2 C1148.2 C1149.2 C1150.2 C1151.2 C1152.2 C5174.1 C5175.1 C5176.2 C5184.2 C5197.2 C5213.2 C5214.2 C5215.2 C5216.2 C5217.2 C5218.2 C5219.2 C5220.2 C5221.2 C5222.2 C5223.2 C5224.2 C5225.2 C5226.2 C5227.2 C5228.2 C5229.2 C5230.2 C5231.2 C5232.2 C5233.2 C5234.2 C5235.2 C5236.2 C5237.2 C5238.2 C5239.2 C5240.2 C5241.2 C5242.2 C5302.2 C5303.2 C5304.2 C5305.2 C5306.2 C5307.2 C5308.2 C5309.2 FB70.1 FB71.1 FB72.1 FL25.2(GND) FL26.2(GND) J16.1A(VEET_1) J16.1B(VEET_1) J16.1C(VEET_1) J16.1D(VEET_1) J16.10A(VEER_1) J16.10B(VEER_1) J16.10C(VEER_1) J16.10D(VEER_1) J16.11A(VEER_2) J16.11B(VEER_2) J16.11C(VEER_2) J16.11D(VEER_2) J16.14A(VEER_3) J16.14B(VEER_3) J16.14C(VEER_3) J16.14D(VEER_3) J16.17A(VEET_2) J16.17B(VEET_2) J16.17C(VEET_2) J16.17D(VEET_2) J16.20A(VEET_3) J16.20B(VEET_3) J16.20C(VEET_3) J16.20D(VEET_3) R730.2 R731.2 R926.1 R927.1 R930.1 R935.1 R936.1 R939.1 R944.1 R945.1 R948.1 R953.1 R954.1 R957.1 R5751.2 R5754.2 R5791.1 R5793.1 R5816.2 R5818.2 R5819.2 R5820.2 R5829.2 R5830.2 R5831.2 R5832.2 R5837.2 R5876.1 R5877.1 R5878.1 R5879.1 R5880.1 R5881.1 R5882.1 R5883.1 R5890.2 R5891.2 U42.67(VSS) U42.129(EPAD) U65.22(GND1) U65.27(GND2) U65.30(GND3) U65.31(GND4) U65.34(GND5) U65.39(GND6) U65.49(DAP_(PAD_GND)) U622.22(GND1) U622.27(GND2) U622.30(GND3) U622.31(GND4) U622.34(GND5) U622.39(GND6) U622.49(DAP_(PAD_GND)) U624.9(VSS) U624.18(AD0) U624.23(AD1) U624.24(AD2) U624.25(EPAD) ; also on sheet 6 7 8 9 10 11 12 13 14 15 16 18 19 20 21 22 24 25 27 28 29 30 31 32 33 34 35 36 43 44 45 46 47 48 49 50 51 52 53 54
P3V3_SFP+_1: C1142.1 C1143.1 J16.15A(VCCR) J16.16A(VCCT) L29.2 R922.1 R923.2 R924.2 R925.1 R1082.1
P3V3_SFP+_2: C1145.1 C1146.1 J16.15B(VCCR) J16.16B(VCCT) L30.2 R931.1 R932.2 R933.2 R934.1 R938.1
P3V3_SFP+_3: C1148.1 C1149.1 J16.15C(VCCR) J16.16C(VCCT) L31.2 R940.1 R941.2 R942.2 R943.1 R947.1
P3V3_SFP+_4: C1151.1 C1152.1 J16.15D(VCCR) J16.16D(VCCT) L32.2 R949.1 R950.2 R951.2 R952.1 R956.1
VCC_3.3: C1141.1 C1144.1 C1147.1 C1150.1 C5309.1 FB89.1 FB90.1 L29.1 L30.1 L31.1 L32.1 U624.21(VDD) ; also on sheet 6 12 13 16 18 24 25 31 32 33 36 43 44 47 48 49 50 51 53
VDD_S1VDD: R733.2 ; also on sheet 19
VDD_S2VDD: R727.2 ; also on sheet 19
VDD_X1VDD: R738.2 ; also on sheet 19
VDD_X2VDD: R737.2 ; also on sheet 19
1G_P0_LED_ACT_N: TP230.1(TP) U42.100(P0_LED[0]) ; also on sheet 44
1G_P0_LINK10_100_N: R5796.1 TP231.1(TP) U42.101(P0_LED[1]) ; also on sheet 44
1G_P0_LINK1000_N: TP232.1(TP) U42.102(P0_LED[2]) ; also on sheet 44
1G_P0_TXVA_N: U42.127(P0_MDIN[0]) ; also on sheet 44
1G_P0_TXVA_P: U42.126(P0_MDIP[0]) ; also on sheet 44
1G_P0_TXVB_N: U42.3(P0_MDIN[1]) ; also on sheet 44
1G_P0_TXVB_P: U42.2(P0_MDIP[1]) ; also on sheet 44
1G_P0_TXVC_N: U42.5(P0_MDIN[2]) ; also on sheet 44
1G_P0_TXVC_P: U42.4(P0_MDIP[2]) ; also on sheet 44
1G_P0_TXVD_N: U42.8(P0_MDIN[3]) ; also on sheet 44
1G_P0_TXVD_P: U42.7(P0_MDIP[3]) ; also on sheet 44
1G_P1_LED_ACT_N: TP237.1(TP) U42.105(P1_LED[0]) ; also on sheet 44
1G_P1_LINK10_100_N: TP236.1(TP) U42.106(P1_LED[1]) ; also on sheet 44
1G_P1_LINK1000_N: TP235.1(TP) U42.107(P1_LED[2]) ; also on sheet 44
1G_P1_TXVA_N: U42.18(P1_MDIN[0]) ; also on sheet 44
1G_P1_TXVA_P: U42.19(P1_MDIP[0]) ; also on sheet 44
1G_P1_TXVB_N: U42.15(P1_MDIN[1]) ; also on sheet 44
1G_P1_TXVB_P: U42.16(P1_MDIP[1]) ; also on sheet 44
1G_P1_TXVC_N: U42.12(P1_MDIN[2]) ; also on sheet 44
1G_P1_TXVC_P: U42.13(P1_MDIP[2]) ; also on sheet 44
1G_P1_TXVD_N: U42.9(P1_MDIN[3]) ; also on sheet 44
1G_P1_TXVD_P: U42.10(P1_MDIP[3]) ; also on sheet 44
1G_P2_LED_ACT_N: TP241.1(TP) U42.111(P2_LED[0]) ; also on sheet 44
1G_P2_LINK10_100_N: TP240.1(TP) U42.112(P2_LED[1]) ; also on sheet 44
1G_P2_LINK1000_N: TP239.1(TP) U42.115(P2_LED[2]) ; also on sheet 44
1G_P2_TXVA_N: U42.21(P2_MDIN[0]) ; also on sheet 44
1G_P2_TXVA_P: U42.20(P2_MDIP[0]) ; also on sheet 44
1G_P2_TXVB_N: U42.24(P2_MDIN[1]) ; also on sheet 44
1G_P2_TXVB_P: U42.23(P2_MDIP[1]) ; also on sheet 44
1G_P2_TXVC_N: U42.27(P2_MDIN[2]) ; also on sheet 44
1G_P2_TXVC_P: U42.26(P2_MDIP[2]) ; also on sheet 44
1G_P2_TXVD_N: U42.30(P2_MDIN[3]) ; also on sheet 44
1G_P2_TXVD_P: U42.29(P2_MDIP[3]) ; also on sheet 44
1G_P3_LED_ACT_N: TP245.1(TP) U42.118(P3_LED[0]) ; also on sheet 44
1G_P3_LINK10_100_N: TP244.1(TP) U42.119(P3_LED[1]) ; also on sheet 44
1G_P3_LINK1000_N: TP243.1(TP) U42.120(P3_LED[2]) ; also on sheet 44
1G_P3_TXVA_N: U42.40(P3_MDIN[0]) ; also on sheet 44
1G_P3_TXVA_P: U42.41(P3_MDIP[0]) ; also on sheet 44
1G_P3_TXVB_N: U42.36(P3_MDIN[1]) ; also on sheet 44
1G_P3_TXVB_P: U42.37(P3_MDIP[1]) ; also on sheet 44
1G_P3_TXVC_N: U42.34(P3_MDIN[2]) ; also on sheet 44
1G_P3_TXVC_P: U42.35(P3_MDIP[2]) ; also on sheet 44
1G_P3_TXVD_N: U42.31(P3_MDIN[3]) ; also on sheet 44
1G_P3_TXVD_P: U42.32(P3_MDIP[3]) ; also on sheet 44
CGND: FB70.2 FB71.2 FB72.2 J16.S1 J16.S2 J16.S3 J16.S4 J16.S5 J16.S6 J16.S7 J16.S8 J16.S9 J16.S10 J16.S11 J16.S12 J16.S13 J16.S14 J16.S15 J16.S16 J16.S17 J16.S18 J16.S19 J16.S20 J16.S21 J16.S22 J16.S23 J16.S24 J16.S25 J16.S26 J16.S27 J16.S28 J16.S29 J16.S30 J16.S31 J16.S32 J16.S33 J16.S34 ; also on sheet 36 44 49 52
CLK_ENET1: U42.66(REF_CLKP) ; also on sheet 24
CLK_RETIMER: U65.19(REFCLK_IN) ; also on sheet 24
I2C1_CH0_SCL: U65.17(SDC) U622.17(SDC) ; also on sheet 50
I2C1_CH0_SDA: U65.18(SDA) U622.18(SDA) ; also on sheet 50
I2C1_CH1_SCL: J16.5A(SCL) ; also on sheet 50
I2C1_CH1_SDA: J16.4A(SDA) ; also on sheet 50
I2C1_CH2_SCL: J16.5B(SCL) ; also on sheet 50
I2C1_CH2_SDA: J16.4B(SDA) ; also on sheet 50
I2C1_CH3_SCL: J16.5C(SCL) ; also on sheet 50
I2C1_CH3_SDA: J16.4C(SDA) ; also on sheet 50
I2C1_CH4_SCL: J16.5D(SCL) ; also on sheet 50
I2C1_CH4_SDA: J16.4D(SDA) ; also on sheet 50
I2C1_CH7_SCL: U624.19(SCL) ; also on sheet 50
I2C1_CH7_SDA: U624.20(SDA) ; also on sheet 50
INT_PHY0_B: U42.99(~{INT}) ; also on sheet 8
INT_RETIMER_B: U65.43(~{INT}) U622.43(~{INT}) ; also on sheet 8
PHY0_AVDD18: C5197.1 C5231.1 C5232.1 C5233.1 C5234.1 C5235.1 C5236.1 C5237.1 C5238.1 C5239.1 C5240.1 C5241.1 C5242.1 FB91.2 U42.6(AVDD18_1) U42.11(AVDD18_2) U42.17(AVDD18_3) U42.22(AVDD18_4) U42.28(AVDD18_5) U42.33(AVDD18_6) U42.39(AVDD18_7) U42.70(AVDD18_8) U42.75(AVDD18_9) U42.78(AVDD18_10) U42.89(AVDD18_11) U42.94(AVDD18_12) U42.128(AVDD18_13)
PHY0_AVDD33: C5184.1 C5227.1 C5228.1 C5229.1 C5230.1 FB90.2 U42.1(AVDD33) U42.14(AVDD33_2) U42.25(AVDD33_3) U42.38(AVDD33_4)
PHY0_CF0: R5793.2 U42.122(CONFIG[0])
PHY0_CF1: R5794.2 U42.123(CONFIG[1])
PHY0_CF2: R5795.2 U42.124(CONFIG[2])
PHY0_CF3: R5796.2 U42.125(CONFIG[3])
PHY0_CKRN: C5176.1 U42.65(REF_CLKN)
PHY0_CLKSEL0: R5755.2 U42.51(CLK_SEL[0])
PHY0_CLKSEL1: R5753.2 R5754.1 U42.52(CLK_SEL[1])
PHY0_HTN: TP224.1(TP) U42.44(HSDACN)
PHY0_HTP: TP223.1(TP) U42.45(HSDACP)
PHY0_NTRST: TP229.1(TP) U42.62(~{TRST})
PHY0_RSET: R5751.1 U42.42(RSET)
PHY0_TCK: TP225.1(TP) U42.54(TCK)
PHY0_TDI: TP226.1(TP) U42.58(TDI)
PHY0_TDO: TP227.1(TP) U42.61(TDO)
PHY0_TMS: TP228.1(TP) U42.55(TMS)
PHY0_VDDORL: C5214.1 C5215.1 C5216.1 C5217.1 C5218.1 FB89.2 R5753.1 R5755.1 R5794.1 R5795.1 U42.56(VDDOR1) U42.64(VDDOR2) U42.83(VDDOM) U42.98(VDDOL1) U42.110(VDDOL2) U42.117(VDDOL3)
PHY_1V0: FB93.1 ; also on sheet 14 43
PHY_1V8: FB91.1 FB92.1 ; also on sheet 15 43
PHY_EMI1_MDC: U42.82(MDC) ; also on sheet 43 45
PHY_EMI1_MDIO: U42.81(MDIO) ; also on sheet 43 45
PORT1_TX_DISABLE: R928.1 U624.1(P00)
PORT1_TXFAULT: J16.2A(TX_FAULT) R1082.2 U624.10(P10)
PORT2_TX_DISABLE: R937.1 U624.2(P01)
PORT2_TXFAULT: J16.2B(TX_FAULT) R938.2 U624.11(P11)
PORT3_TX_DISABLE: R946.1 U624.3(P02)
PORT3_TXFAULT: J16.2C(TX_FAULT) R947.2 U624.12(P12)
PORT4_TX_DISABLE: R955.2 U624.4(P03)
PORT4_TXFAULT: J16.2D(TX_FAULT) R956.2 U624.13(P13)
R_SD1_RX0_N: R5877.2 U22.D15(~{SD1_RX0})
R_SD1_RX0_P: R5876.2 U22.C15(SD1_RX0)
R_SD1_RX1_N: R5879.2 U22.B16(~{SD1_RX1})
R_SD1_RX1_P: R5878.2 U22.A16(SD1_RX1)
R_SD1_RX2_N: R5881.2 U22.D17(~{SD1_RX2})
R_SD1_RX2_P: R5880.2 U22.C17(SD1_RX2)
R_SD1_RX3_N: R5883.2 U22.B18(~{SD1_RX3})
R_SD1_RX3_P: R5882.2 U22.A18(SD1_RX3)
R_SD1_RX4_N: C443.1 R532.2 U22.D19(~{SD1_RX4})
R_SD1_RX4_P: C444.1 R532.1 U22.C19(SD1_RX4)
R_SD1_RX5_N: C445.1 R533.2 U22.B20(~{SD1_RX5})
R_SD1_RX5_P: C446.1 R533.1 U22.A20(SD1_RX5)
R_SD1_RX6_N: C448.1 R534.2 U22.D21(~{SD1_RX6})
R_SD1_RX6_P: C447.1 R534.1 U22.C21(SD1_RX6)
R_SD1_RX7_N: C449.1 R535.2 U22.B22(~{SD1_RX7})
R_SD1_RX7_P: C450.1 R535.1 U22.A22(SD1_RX7)
R_SD2_RX4_N: C451.1 R536.2 U22.D27(~{SD2_RX4})
R_SD2_RX4_P: C452.1 R536.1 U22.C27(SD2_RX4)
R_SD2_RX5_N: C453.1 R537.2 U22.B28(~{SD2_RX5})
R_SD2_RX5_P: C454.1 R537.1 U22.A28(SD2_RX5)
R_SD2_RX6_N: C456.1 R538.2 U22.D29(~{SD2_RX6})
R_SD2_RX6_P: C455.1 R538.1 U22.C29(SD2_RX6)
R_SD2_RX7_N: C457.1 R539.2 U22.B30(~{SD2_RX7})
R_SD2_RX7_P: C458.1 R539.1 U22.A30(SD2_RX7)
R_SD2_TX0_N: C230.1 U22.J23(~{SD2_TX0})
R_SD2_TX0_P: C231.1 U22.H23(SD2_TX0)
R_SD2_TX1_N: C228.1 U22.G24(~{SD2_TX1})
R_SD2_TX1_P: C229.1 U22.F24(SD2_TX1)
R_SD2_TX2_N: C226.1 U22.J25(~{SD2_TX2})
R_SD2_TX2_P: C227.1 U22.H25(SD2_TX2)
R_SD2_TX3_N: C224.1 U22.G26(~{SD2_TX3})
R_SD2_TX3_P: C225.1 U22.F26(SD2_TX3)
RST_I2CMUX_B: U624.22(~{RESET}) ; also on sheet 8 50
RST_PHY_1G_B: U42.97(~{RESET}) ; also on sheet 8 43
RT1_2V5: C1109.1 C1110.1 C1111.1 C1112.1 C1113.1 C5302.1 FL25.3(OUT_IN) U65.3(VDD1) U65.6(VDD2) U65.7(VDD3) U65.10(VDD4) U65.15(VDD5) U65.46(VDD6)
RT1_ADDR0: R5825.2 R5829.1 U65.45(LOCK_0/ADDR_0)
RT1_ADDR1: R5826.2 R5830.1 U65.40(LOCK_1/ADDR_1)
RT1_ADDR2: R5827.2 R5831.1 U65.21(LOCK_2/ADDR_2)
RT1_ADDR3: R5828.2 R5832.1 U65.16(LOCK_3/ADDR_3)
RT2_2V5: C5303.1 C5304.1 C5305.1 C5306.1 C5307.1 C5308.1 FL26.3(OUT_IN) U622.3(VDD1) U622.6(VDD2) U622.7(VDD3) U622.10(VDD4) U622.15(VDD5) U622.46(VDD6)
RT2_ADDR0: R5817.2 R5837.1 U622.45(LOCK_0/ADDR_0)
RT2_ADDR1: R5818.1 R5838.2 U622.40(LOCK_1/ADDR_1)
RT2_ADDR2: R5819.1 R5839.2 U622.21(LOCK_2/ADDR_2)
RT2_ADDR3: R5820.1 R5840.2 U622.16(LOCK_3/ADDR_3)
RX1_L0_N: C1209.1 U65.5(RXN1)
RX1_L0_N_DC: C1209.2 J16.12A(RD-)
RX1_L0_P: C1208.1 U65.4(RXP1)
RX1_L0_P_DC: C1208.2 J16.13A(RD+)
RX1_LOS: J16.8A(RX_LOS) R922.2 U624.14(P14)
RX2_L0_N: C1212.1 U65.12(RXN3)
RX2_L0_N_DC: C1212.2 J16.12B(RD-)
RX2_L0_P: C1213.1 U65.11(RXP3)
RX2_L0_P_DC: C1213.2 J16.13B(RD+)
RX2_LOS: J16.8B(RX_LOS) R931.2 U624.15(P15)
RX3_L0_N: C1217.1 U622.5(RXN1)
RX3_L0_N_DC: C1217.2 J16.12C(RD-)
RX3_L0_P: C1216.1 U622.4(RXP1)
RX3_L0_P_DC: C1216.2 J16.13C(RD+)
RX3_LOS: J16.8C(RX_LOS) R940.2 U624.16(P16)
RX4_L0_N: C1220.1 U622.12(RXN3)
RX4_L0_N_DC: C1220.2 J16.12D(RD-)
RX4_L0_P: C1221.1 U622.11(RXP3)
RX4_L0_P_DC: C1221.2 J16.13D(RD+)
RX4_LOS: J16.8D(RX_LOS) R949.2 U624.17(P17)
SD1_IMP_CAL_RX: R733.1 U22.M16(SD1_IMP_CAL_RX)
SD1_IMP_CAL_TX: R738.1 U22.M22(SD1_IMP_CAL_TX)
SD1_PLL1_TPA: TP88.1(TP) U22.M18(SD1_PLL1_TPA)
SD1_PLL1_TPD: TP91.1(TP) U22.L16(SD1_PLL1_TPD)
SD1_PLL2_TPA: TP92.1(TP) U22.M20(SD1_PLL2_TPA)
SD1_PLL2_TPD: TP95.1(TP) U22.L22(SD1_PLL2_TPD)
SD1_REF_CLK2_N: R5891.1 U22.N21(~{SD1_REF_CLK2})
SD1_REF_CLK2_P: R5890.1 U22.P21(SD1_REF_CLK2)
SD1_REFCLK1_N: U22.P19(~{SD1_REF_CLK1}) ; also on sheet 25
SD1_REFCLK1_P: U22.P18(SD1_REF_CLK1) ; also on sheet 25
SD1_RX4_N: C443.2 U42.92(P0_S_OUTN)
SD1_RX4_P: C444.2 U42.93(P0_S_OUTP)
SD1_RX5_N: C445.2 U42.91(P1_S_OUTN)
SD1_RX5_P: C446.2 U42.90(P1_S_OUTP)
SD1_RX6_N: C448.2 U42.73(P2_S_OUTN)
SD1_RX6_P: C447.2 U42.74(P2_S_OUTP)
SD1_RX7_N: C449.2 U42.72(P3_S_OUTN)
SD1_RX7_P: C450.2 U42.71(P3_S_OUTP)
SD1_TX4_N: U22.J19(~{SD1_TX4}) U42.95(P0_S_INN)
SD1_TX4_P: U22.H19(SD1_TX4) U42.96(P0_S_INP)
SD1_TX5_N: U22.G20(~{SD1_TX5}) U42.88(P1_S_INN)
SD1_TX5_P: U22.F20(SD1_TX5) U42.87(P1_S_INP)
SD1_TX6_N: U22.J21(~{SD1_TX6}) U42.76(P2_S_INN)
SD1_TX6_P: U22.H21(SD1_TX6) U42.77(P2_S_INP)
SD1_TX7_N: U22.G22(~{SD1_TX7}) U42.69(P3_S_INN)
SD1_TX7_P: U22.F22(SD1_TX7) U42.68(P3_S_INP)
SD2_IMP_CAL_RX: R727.1 U22.M23(SD2_IMP_CAL_RX)
SD2_IMP_CAL_TX: R737.1 U22.M29(SD2_IMP_CAL_TX)
SD2_PLL1_TPA: TP94.1(TP) U22.M25(SD2_PLL1_TPA)
SD2_PLL1_TPD: TP93.1(TP) U22.L23(SD2_PLL1_TPD)
SD2_PLL2_TPA: TP89.1(TP) U22.M27(SD2_PLL2_TPA)
SD2_PLL2_TPD: TP97.1(TP) U22.L29(SD2_PLL2_TPD)
SD2_REFCLK1_N: U22.N24(~{SD2_REF_CLK1}) ; also on sheet 24
SD2_REFCLK1_P: U22.P24(SD2_REF_CLK1) ; also on sheet 24
SD2_REFCLK2_N: R730.1 U22.P26(~{SD2_REF_CLK2}) ; also on sheet 25
SD2_REFCLK2_P: R731.1 U22.P27(SD2_REF_CLK2) ; also on sheet 25
SD2_RX0_N: C1033.2 U22.D23(~{SD2_RX0})
SD2_RX0_P: C1032.2 U22.C23(SD2_RX0)
SD2_RX1_N: C1034.2 U22.B24(~{SD2_RX1})
SD2_RX1_P: C1031.2 U22.A24(SD2_RX1)
SD2_RX2_N: C1036.1 U22.D25(~{SD2_RX2})
SD2_RX2_P: C1035.1 U22.C25(SD2_RX2)
SD2_RX3_N: C1038.1 U22.B26(~{SD2_RX3})
SD2_RX3_P: C1037.1 U22.A26(SD2_RX3)
SD2_RX4_N: C451.2 ; also on sheet 43
SD2_RX4_P: C452.2 ; also on sheet 43
SD2_RX5_N: C453.2 ; also on sheet 43
SD2_RX5_P: C454.2 ; also on sheet 43
SD2_RX6_N: C456.2 ; also on sheet 43
SD2_RX6_P: C455.2 ; also on sheet 43
SD2_RX7_N: C457.2 ; also on sheet 43
SD2_RX7_P: C458.2 ; also on sheet 43
SD2_TX0_N: C230.2 U65.2(RXN0)
SD2_TX0_P: C231.2 U65.1(RXP0)
SD2_TX1_N: C228.2 U65.9(RXN2)
SD2_TX1_P: C229.2 U65.8(RXP2)
SD2_TX2_N: C226.2 U622.2(RXN0)
SD2_TX2_P: C227.2 U622.1(RXP0)
SD2_TX3_N: C224.2 U622.9(RXN2)
SD2_TX3_P: C225.2 U622.8(RXP2)
SD2_TX4_N: U22.J27(~{SD2_TX4}) ; also on sheet 43
SD2_TX4_P: U22.H27(SD2_TX4) ; also on sheet 43
SD2_TX5_N: U22.G28(~{SD2_TX5}) ; also on sheet 43
SD2_TX5_P: U22.F28(SD2_TX5) ; also on sheet 43
SD2_TX6_N: U22.J29(~{SD2_TX6}) ; also on sheet 43
SD2_TX6_P: U22.H29(SD2_TX6) ; also on sheet 43
SD2_TX7_N: U22.G30(~{SD2_TX7}) ; also on sheet 43
SD2_TX7_P: U22.F30(SD2_TX7) ; also on sheet 43
SP1_MODA: J16.6A(MOD_ABS) R925.2
SP1_RS0: J16.9A(RS1) R923.1 R926.2
SP1_RS1: J16.7A(RS0) R924.1 R927.2
SP1_TXDIS: J16.3A(TX_DISABLE) R928.2 R930.2
SP2_MODA: J16.6B(MOD_ABS) R934.2
SP2_RS0: J16.9B(RS1) R932.1 R935.2
SP2_RS1: J16.7B(RS0) R933.1 R936.2
SP2_TXDIS: J16.3B(TX_DISABLE) R937.2 R939.2
SP3_MODA: J16.6C(MOD_ABS) R943.2
SP3_RS0: J16.9C(RS1) R941.1 R944.2
SP3_RS1: J16.7C(RS0) R942.1 R945.2
SP3_TXDIS: J16.3C(TX_DISABLE) R946.2 R948.2
SP4_MODA: J16.6D(MOD_ABS) R952.2
SP4_RS0: J16.9D(RS1) R951.1 R954.2
SP4_RS1: J16.7D(RS0) R950.1 R953.2
SP4_TXDIS: J16.3D(TX_DISABLE) R955.1 R957.2
TX1_L0_N: C1211.1 U65.35(TXN0)
TX1_L0_N_DC: C1211.2 J16.19A(TD-)
TX1_L0_P: C1210.1 U65.36(TXP0)
TX1_L0_P_DC: C1210.2 J16.18A(TD+)
TX2_L0_N: C1215.1 U65.28(TXN2)
TX2_L0_N_DC: C1215.2 J16.19B(TD-)
TX2_L0_P: C1214.1 U65.29(TXP2)
TX2_L0_P_DC: C1214.2 J16.18B(TD+)
TX3_L0_N: C1219.1 U622.35(TXN0)
TX3_L0_N_DC: C1219.2 J16.19C(TD-)
TX3_L0_P: C1218.1 U622.36(TXP0)
TX3_L0_P_DC: C1218.2 J16.18C(TD+)
TX4_L0_N: C1223.1 U622.28(TXN2)
TX4_L0_N_DC: C1223.2 J16.19D(TD-)
TX4_L0_P: C1222.1 U622.29(TXP2)
TX4_L0_P_DC: C1222.2 J16.18D(TD+)
XFCFG_CLKO: U65.42(REFCLK_OUT) U622.19(REFCLK_IN)
XFCFG_ENSMB: R5815.2 U65.20(EN_SMB) U622.20(EN_SMB)
XFCFG_READEN: R5816.1 U65.44(~{READ_EN}) U622.44(~{READ_EN})
XRT_CP0: C5316.1 U65.47(LPF_CP_0)
XRT_CP1: C5317.1 U65.38(LPF_CP_1)
XRT_CP2: C5318.1 U65.23(LPF_CP_2)
XRT_CP3: C5319.1 U65.14(LPF_CP_3)
XRT_CP4: C5312.1 U622.47(LPF_CP_0)
XRT_CP5: C5313.1 U622.38(LPF_CP_1)
XRT_CP6: C5314.1 U622.23(LPF_CP_2)
XRT_CP7: C5315.1 U622.14(LPF_CP_3)
XRT_REF0: C5316.2 U65.48(LPF_REF_0)
XRT_REF1: C5317.2 U65.37(LPF_REF_1)
XRT_REF2: C5318.2 U65.24(LPF_REF_2)
XRT_REF3: C5319.2 U65.13(LPF_REF_3)
XRT_REF4: C5312.2 U622.48(LPF_REF_0)
XRT_REF5: C5313.2 U622.37(LPF_REF_1)
XRT_REF6: C5314.2 U622.24(LPF_REF_2)
XRT_REF7: C5315.2 U622.13(LPF_REF_3)
XRX1_DOUTN: C1033.1 U65.32(TXN1)
XRX1_DOUTP: C1032.1 U65.33(TXP1)
XRX2_DOUTN: C1034.1 U65.25(TXN3)
XRX2_DOUTP: C1031.1 U65.26(TXP3)
XRX3_DOUTN: C1036.2 U622.32(TXN1)
XRX3_DOUTP: C1035.2 U622.33(TXP1)
XRX4_DOUTN: C1038.2 U622.25(TXN3)
XRX4_DOUTP: C1037.2 U622.26(TXP3)
N32074313: C5174.2 U42.49(XTAL_IN) Y20.1
N32074325: C5175.2 U42.50(XTAL_OUT) Y20.2
N32105138: C472.1 C5219.1 C5220.1 C5221.1 C5222.1 C5223.1 C5224.1 C5225.1 C5226.1 FB93.2 U42.53(DVDD1) U42.57(DVDD2) U42.63(DVDD3) U42.79(DVDD4) U42.86(DVDD5) U42.104(DVDD6) U42.109(DVDD7) U42.113(DVDD8)
N32110539: R5791.2 U42.114(V18_L)
N32112200: C5213.1 FB92.2 U42.43(VDDC1) U42.48(VDDC2)
N32113835: TP233.1(TP) U42.103(P0_LED[3])
N32113861: TP234.1(TP) U42.108(P1_LED[3])
N32113887: TP238.1(TP) U42.116(P2_LED[3])
N32114066: TP242.1(TP) U42.121(P3_LED[3])

Not connected (* = marked no-connect by the designer): U22 F16(SD1_TX1)* F18(SD1_TX3)* G16(~{SD1_TX1})* G18(~{SD1_TX3})* H15(SD1_TX0)* H17(SD1_TX2)* J15(~{SD1_TX0})* J17(~{SD1_TX2})*; U42 46(TSTPT)* 47(NC1)* 59(NC2)* 60(NC3)* 80(TSTPTF)* 84(TEST[1])* 85(TEST[0])*; U65 41(~{ALL_DONE})*; U622 41(~{ALL_DONE})* 42(REFCLK_OUT)*; U624 5(P04)* 6(P05)* 7(P06)* 8(P07)*

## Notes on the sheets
sheet 37
- FRONT SIDE SERDES 1 & 2  (ENET)
- DIFF TERM (OPTIONAL)
- SGMII from 1G PHY #1
- SGMII to 1G PHY #1
- XFI from RETIMER
- XFI to RETIMER
- SGMII to 1G PHY #2
- SGMII from 1G PHY #2
- DIFF TERM (OPTIONAL)
- SerDes 1 configuration
  ====================================================
  RCW[SRDS_PRTCL_S1]=           7 - Unused x4 & 1 G PHY
  PLL mapping=                  11111111
  RCW[SRDS_PLL_PD_S1]=          01
  RCW[SRDS_PLL_REF_CLK_SEL_S1]= 0: PLL1=100MHz
- SerDes 2 configuration
  ====================================================
  RCW[SRDS_PRTCL_S2]=           55 - XFI & 1 G PHY
  PLL mapping=                  11112222
  RCW[SRDS_PLL_PD_S2]=          00
  RCW[SRDS_PLL_REF_CLK_SEL_S2]= 0: PLL1=156.25MHZ & PLL2=100MHz
sheet 38
- 10GE: XFI/SFP Retimer
- I2C Address = 0x18
- I2C Address = 0x19
sheet 39
- SFP Monitor/Control
- I2C Address = 0x20 + 0x7C
sheet 40
- SFP Ports 1 / 2 / Cage
- 500mA
- 500mA
sheet 41
- SFP Ports 3 & 4
- 500mA
- 500mA
sheet 42
- 1GE PHY #1
- SGMII to SERDES 1
- \------------------------------------------------------VDDOL-----------------------------------------------------/
- CONFIGURATION
  =============================
  PHY ADDR = 0x00 ... 0x03
  ADVERTISE= all
  DEFAULT  = powered down, auto-cross, auto-neg
  MODE     = SGMII to Copper
  =============================
  CONFIG0 ::  PHY_ORD=0  PHYAD4=0     PHYAD3=0     PHYAD2=0  => 0000   => to GND
  CONFIG1 ::  SEL_MS=1   ENA_PAUSE=1  CANEG1=1     CANEG0=1  => 1111   => to VDDO
  CONFIG2 ::  SQ_ANEG=1  ENA_XC=1     DIS_SLEEP=1  PDOWN=1   => 1111   => to VDDO
  CONFIG3 ::  RSVD=0     MODE2=0      MODE1=0      MODE0=1   => 0001   => to P0_LED[1]
- VDDOM
- VDDOL
- \---------------------VDDOR--------------------/
- CLK_SEL[1:0]
  ===========
  00= REFCLK(P,N) = 156.25 MHz
  01= REFCLK(P,N) = 125.00 MHz
  10= REFCLK(P,N) = 25.00 MHz
  11= XTAL 25 MHz
- GUARD RING
- V18_L
  0=VDDOL = 2.5V/3.3V
  Z=VDDOL = 1.8V
